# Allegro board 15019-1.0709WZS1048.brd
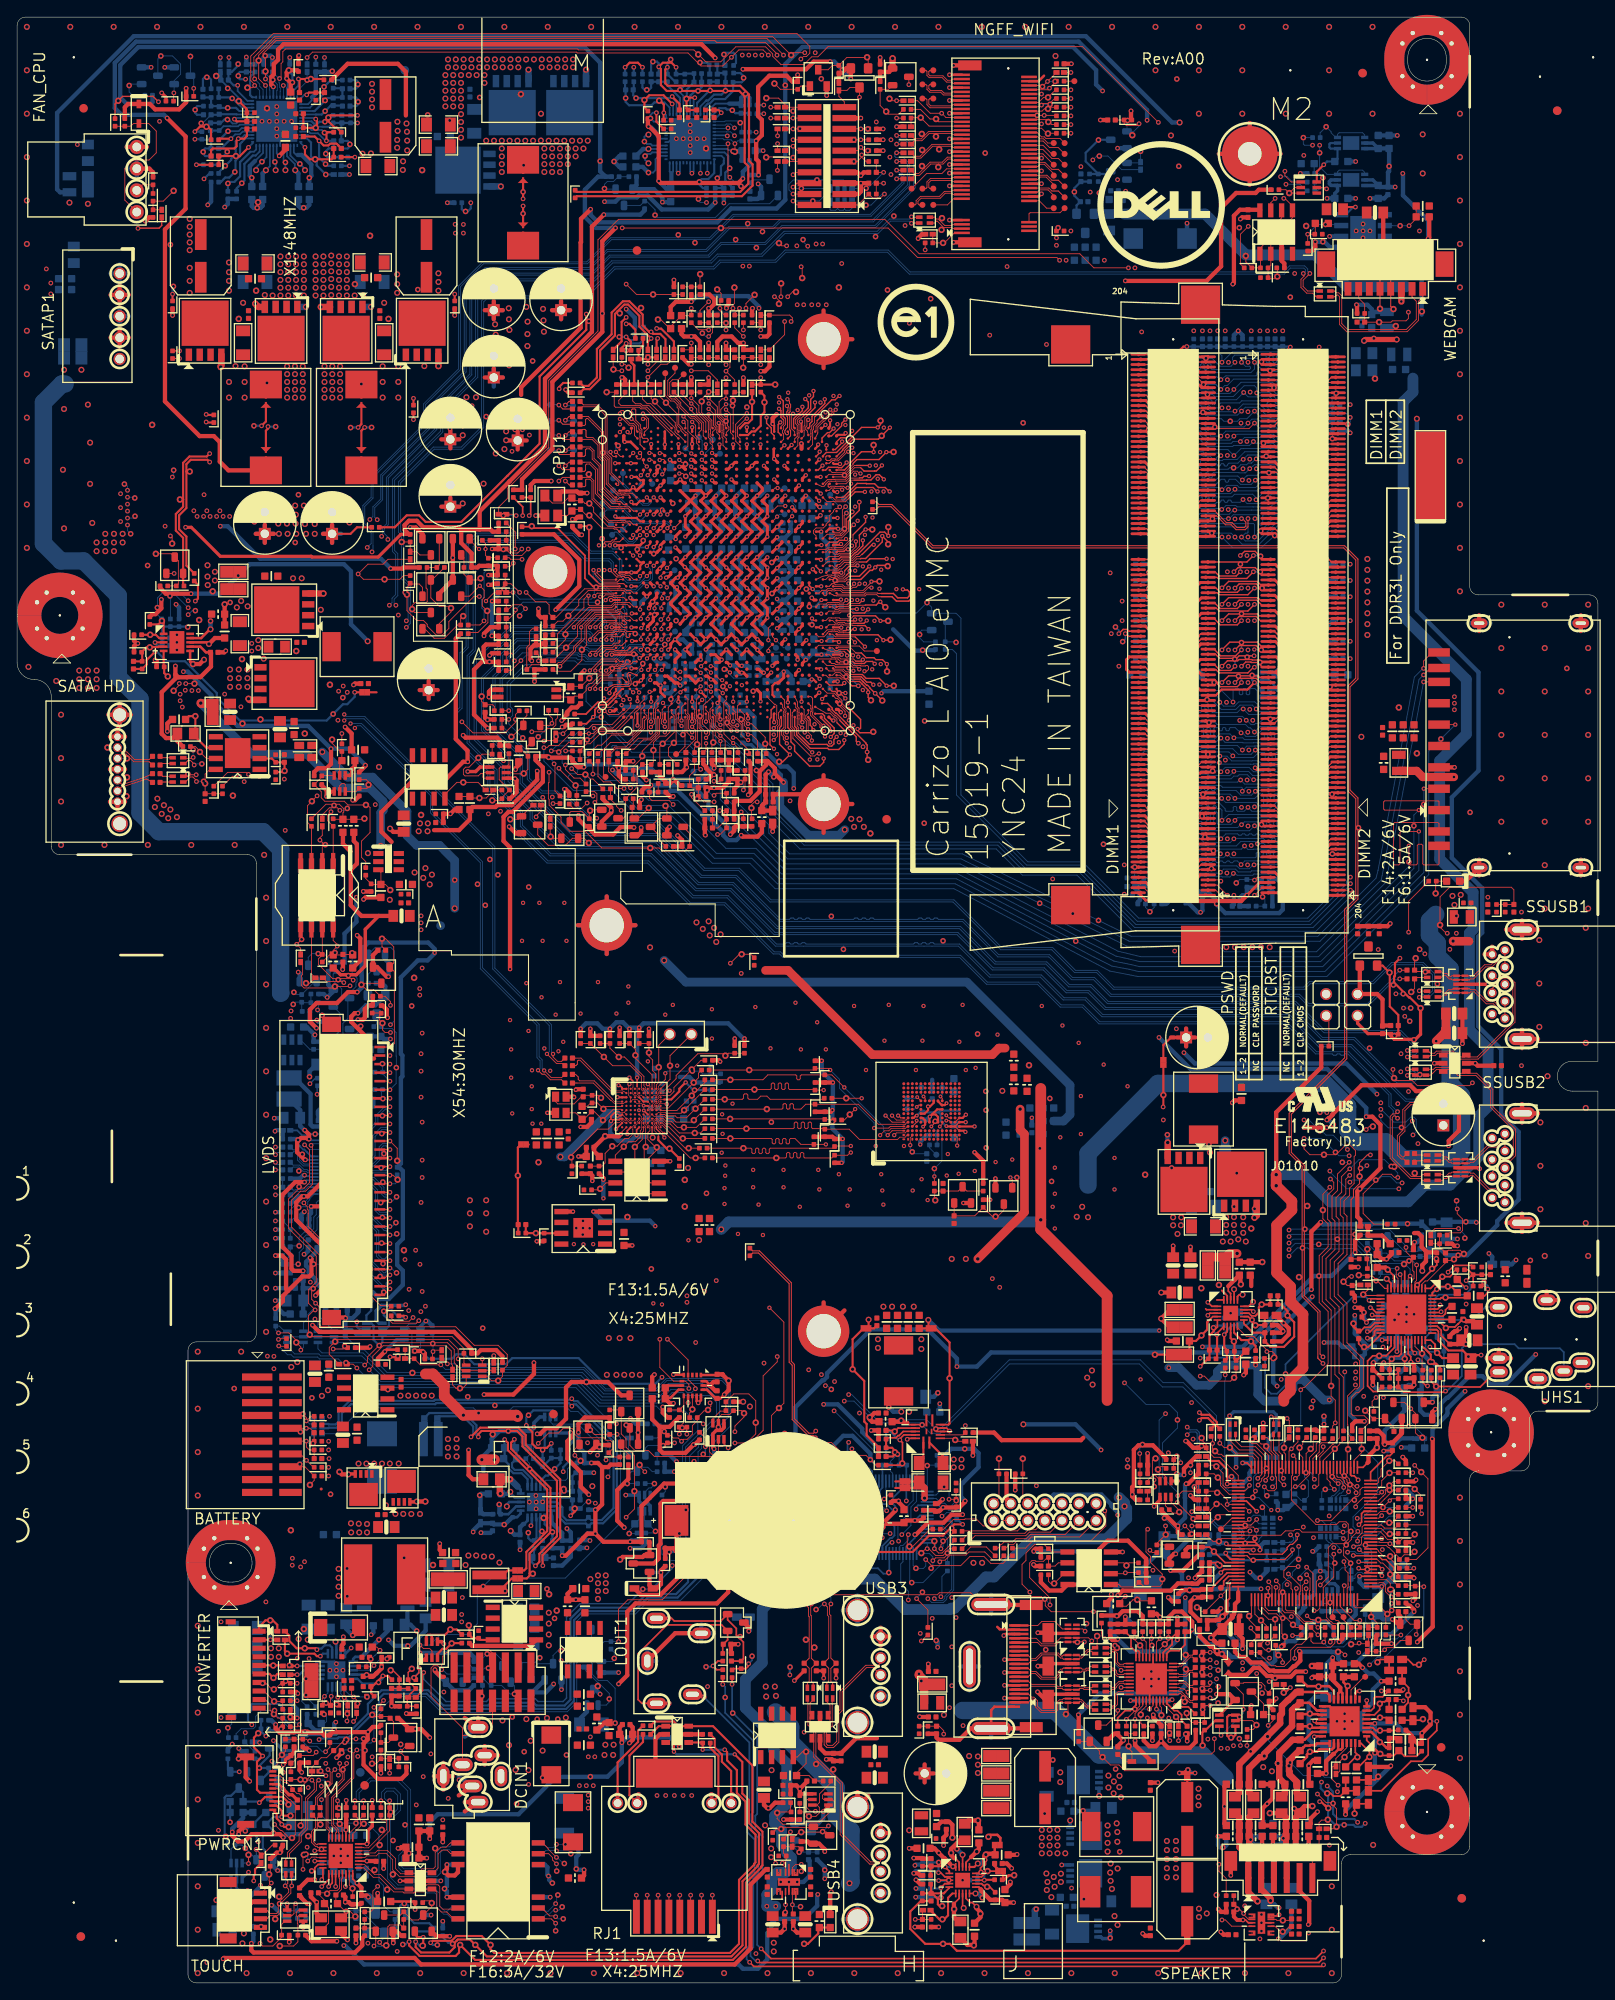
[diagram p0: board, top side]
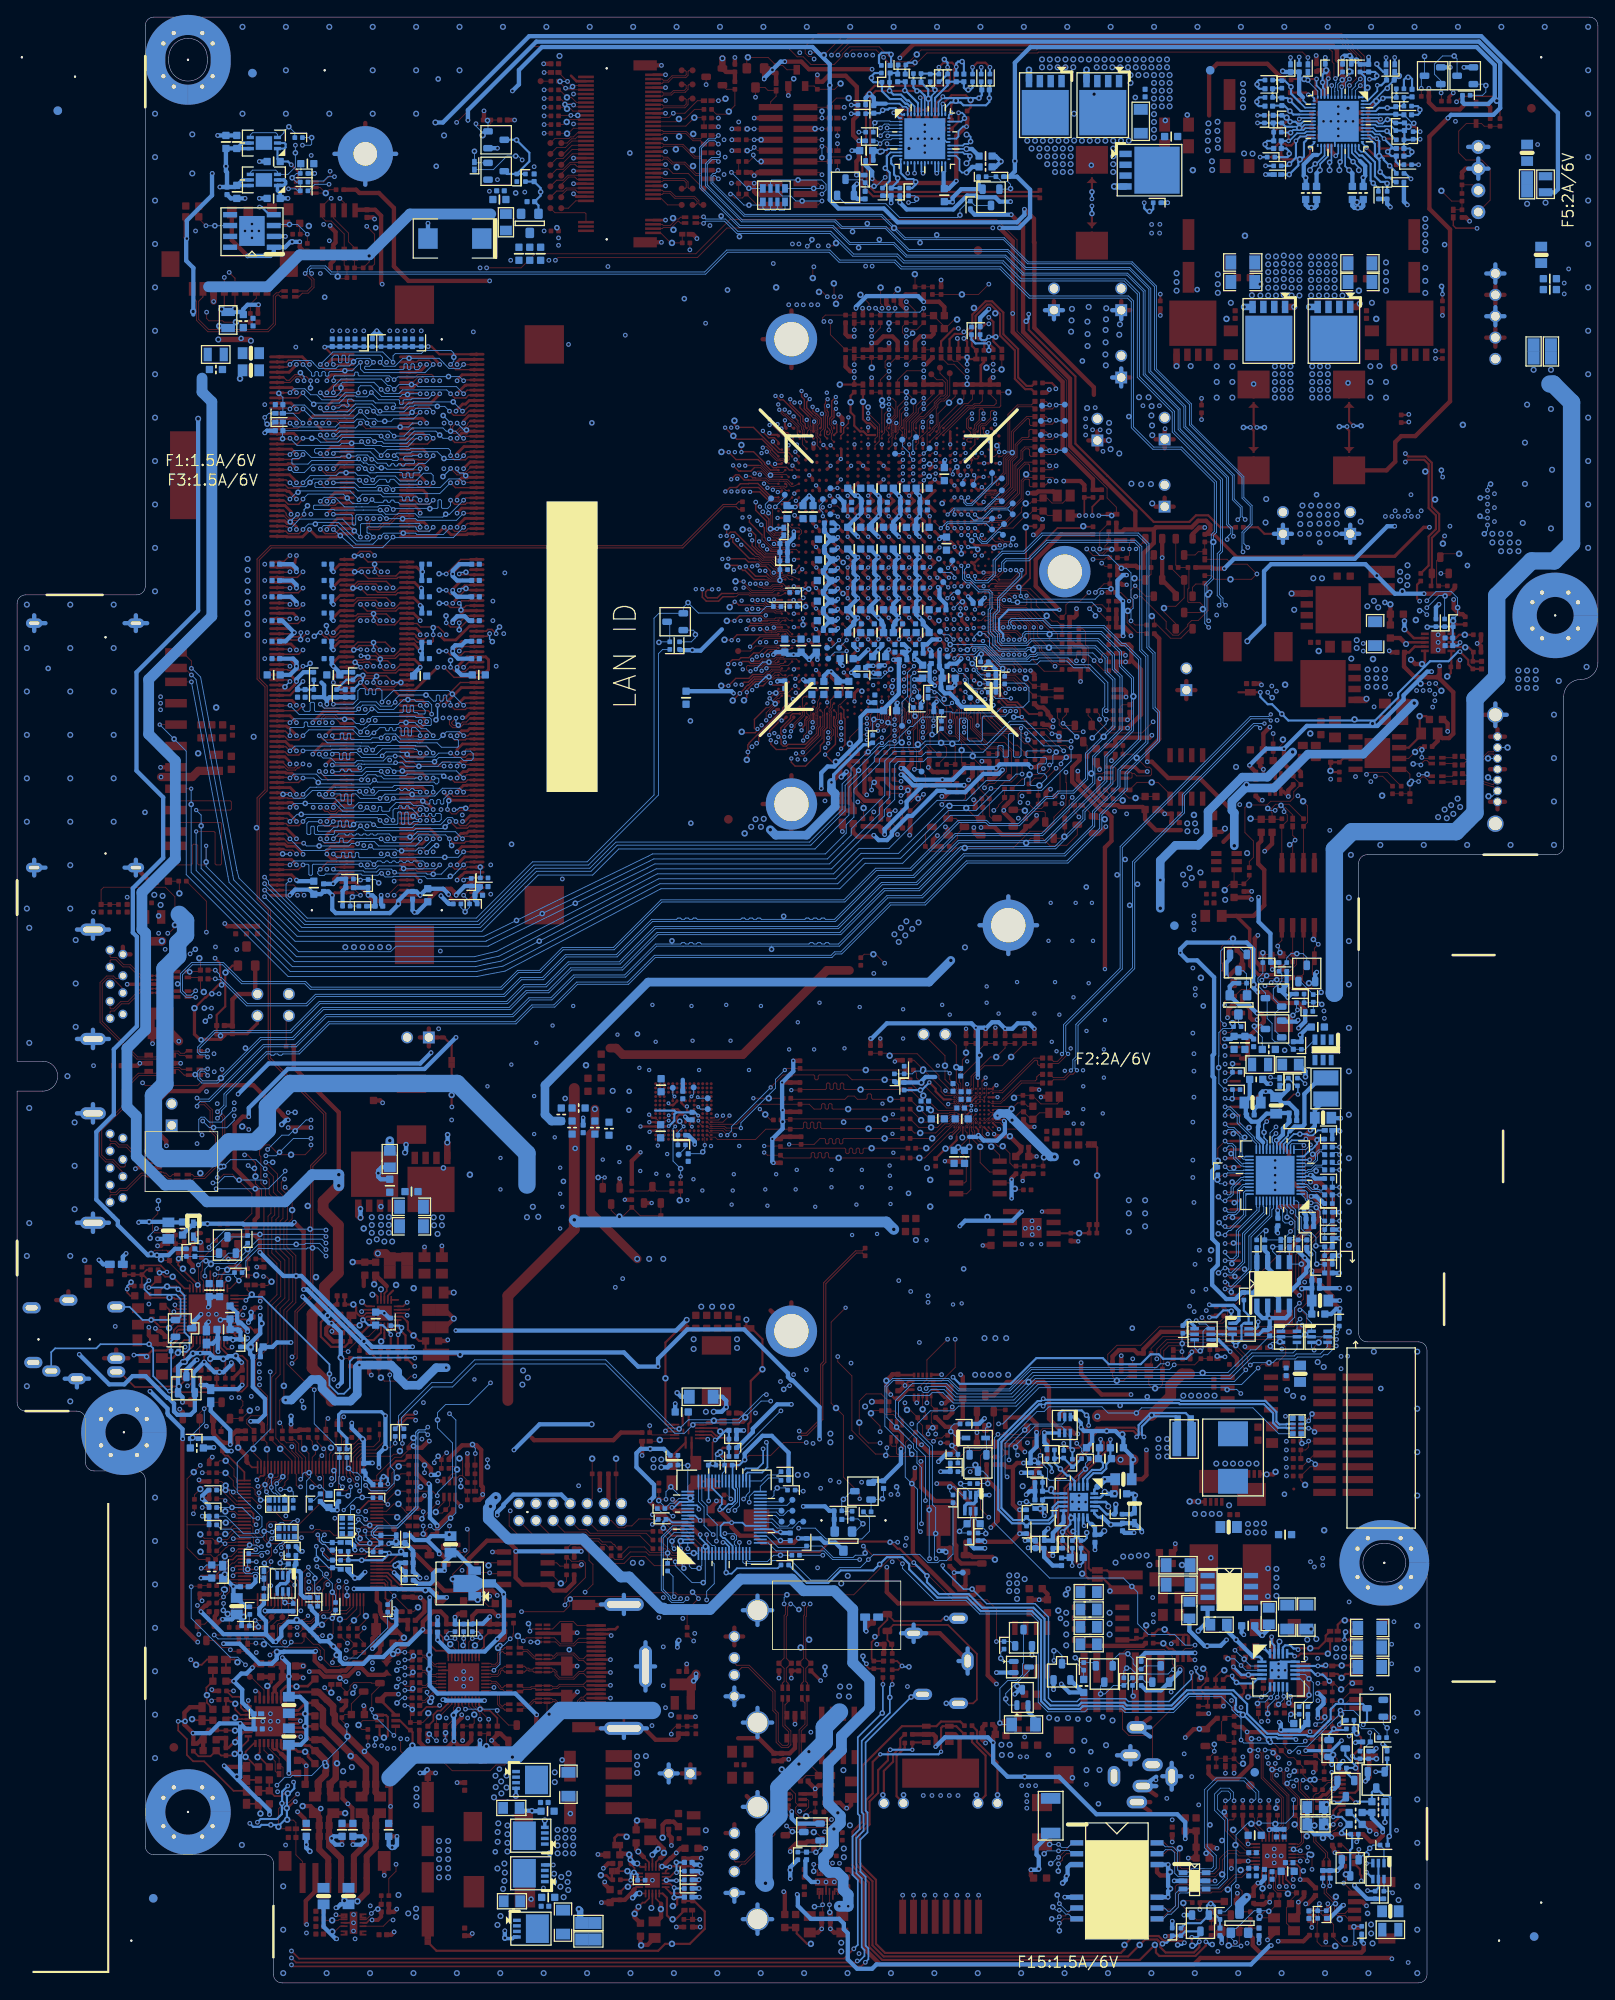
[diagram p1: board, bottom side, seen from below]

Outline 185 x 230 mm; copper layers: TOP, L2GND, L3, L4, L5GND, BOTTOM. Coordinates in mm from the lower left corner of the outline.
Outline path: 0,229 0,154.5 arc(0.59,153.09) 2,152.5 arc(3.41,151.91) 4,150.5 4,133 arc(4.29,132.29) 5,132 27,132 arc(27.71,131.71) 28,131 28,76 arc(27.71,75.29) 27,75 21,75 arc(20.29,74.71) 20,74 20,1 arc(20.29,0.29) 21,0 154,0 arc(154.71,0.29) 155,1 155,14 arc(155.29,14.71) 156,15 169,15 arc(169.71,15.29) 170,16 170,58.9 arc(170.29,59.61) 171,59.9 176,59.9 arc(176.71,60.19) 177,60.9 177,65.9 arc(177.29,66.61) 178,66.9 184,66.9 arc(184.71,67.19) 185,67.9 185,104.34 182,104.34 arc(180.25,106.09) 182,107.84 185,107.84 185,161.4 arc(184.71,162.11) 184,162.4 171,162.4 arc(170.29,162.69) 170,163.4 170,229 arc(169.71,229.71) 169,230 1,230 arc(0.29,229.71) 0,229 ; 24.75,51.4 25.25,51.4 arc(27.5,49.15) 25.25,46.9 24.75,46.9 arc(22.5,49.15) 24.75,51.4 ; 162.75,225.25 arc(165,227.5) 167.25,225.25 167.25,224.75 arc(165,222.5) 162.75,224.75 162.75,225.25

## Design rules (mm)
constraint set DEFAULT: min track width 0.127, pair gap 0.102
net group AUDIO_IO_40: nets RING2 SLEEVE
net group EMMC_POWER_10_10: nets EMMC_VCC1N EMMC_VCC2N
net group EUP-MW: nets EC_EUP EC_EUP_EN
net group GND: nets AMP_GND GND_AUD
net group OSCILLATION-MW: nets LAN_XTALI LAN_XTALO
net group PWR_CHG_SR-DIFF0: nets PWR_CHG_SRN PWR_CHG_SRP
net group SPI_CLK_8-MW: nets SPI_CLK SPI_CLK_1
net group TRANSFORNER_20_10: nets MCT_R_1 XRF_TDC2
net group USB_OC-MW: nets USBOC01* USBOC02*
net group AGND: nets CHG_AGND SIO_AGND TPA3131_GVDD
net group AUDIO_AMP-MW: nets SYNC TPA3131_FAULT# TPA3131_SD TPA3131_SD1#
net group AUDIO_AMP_15: nets AMP_SPKR_L AMP_SPKR_R PORTC_SPK_L PORTC_SPK_L_1 PORTC_SPK_R PORTC_SPK_R_1 SPKR_IN_L SPKR_IN_R TPA3131_GAIN TPA3131_LINN TPA3131_LINN_1 TPA3131_MUTE TPA3131_PLIMIT TPA3131_RINN TPA3131_RINN_1
net group AUDIO_DMIC_MW: nets AUD_DMIC_CLK AUD_DMIC_CLK_R AUD_DMIC_CLK_R_1 AUD_DMIC_DATA AUD_DMIC_DATA_R
net group AUDIO_HDA: nets AUD_BEEP_C AUD_BEEP_R AUD_LINK_BCLK AUD_LINK_RST_N AUD_LINK_RST_N_R AUD_LINK_SDIN AUD_LINK_SDIN_1 AUD_LINK_SDO AUD_LINK_SDO_1 AUD_LINK_SDO_N AUD_LINK_SYNC BUZZER_SPKR_R PCH_AUD_RST_N PCH_AUD_RST_N_1 SENSE_B SLEEVE_G
net group AUDIO_IO: nets AUD_GP3 EAPD_DEPOP HPOL_CON HPOR_CON HPOUT-JD HPOUT-L HPOUT-R LINE2-VREFO LINEOUT-JD LINEOUT-L LINEOUT-R LINEOUT_C-L LINEOUT_C-R LINEOUT_CON-L LINEOUT_CON-R MIC2-L MIC2-L-1 MIC2-R MIC2-R-1 MIC2-VREFO-L MIC2-VREFO-R
net group AUDIO_IO_REF: nets JDREF MIC-CAP VRP
net group AUDIO_SPK_CN: nets SPKR_L+_C SPKR_L+_SNB SPKR_L-_C SPKR_L-_SNB SPKR_OUT_L+ SPKR_OUT_L- SPKR_OUT_R+ SPKR_OUT_R- SPKR_R+_C SPKR_R+_SNB SPKR_R-_C SPKR_R-_SNB TPA3131_BSNL TPA3131_BSNR TPA3131_BSPL TPA3131_BSPR
net group AZ_AUDIO: nets APU_SPKR AZ_BCLK_M AZ_RST_N_M AZ_SDIN1 AZ_SDIN2 AZ_SDOUT_M AZ_SYNC_M
net group CAL_8: nets MEM_MA_ZVDDIO MEM_MB_ZVDDIO P_RX_ZVDD P_TX_ZVDD SATA_CALRN SATA_CALRP USB_COMP_M USBSS_CALRN USBSS_CALRP
net group CHARGER_4_5-MW: nets AC_IN AC_OK# AC_PRES AC_PROTECT AD_IA AD_IA_HW1 AD_IA_HW2 AD_OFF AD_OFF_L BAT_ALERT BAT_IN# BAT_IN#_1 CHG_ON# PD4405_A PD4405_K PQ4206_D PQ4406_2 PQ4406_3 PQ4406_5 PQ4406_6 PQ4409_C PQ4409_E PWR_CHG_AD_OFF PWR_CHG_AD_OFF_R SYS_PRES
net group CLOCK-MWS: nets CK_48M_SIO CK_P_33M_EC CK_P_33M_SIO CLK_48M_SIO_C LPC_CLK0_R LPC_CLK1 LPC_CLK1_R PCH_CLK48_F SUSCLK_32_APU SUSCLK_32_APU_C X32K_X1 X32K_X2 X48M_X1 X48M_X2
net group CONVERTER_4_5-MW: nets LEDC_ISET LPF RT SSTCMP SSTCMP_1 STATUS VREF
net group CONVERTER_10_10: nets ISEN1 ISEN2 ISEN3 ISEN4 ISW OZ554_PWM RTN1 RTN2 RTN3 RTN4
net group CONVERTER_20_10: nets LDR LDR_1 OZ554_VIN SNB
net group DDR3_A_ADDR&CMD-MW: nets M_CAS_A_N M_MAA_A0 M_MAA_A1 M_MAA_A2 M_MAA_A3 M_MAA_A4 M_MAA_A5 M_MAA_A6 M_MAA_A7 M_MAA_A8 M_MAA_A9 M_MAA_A10 M_MAA_A11 M_MAA_A12 M_MAA_A13 M_MAA_A14 M_MAA_A15 M_RAS_A_N M_SBS_A0 M_SBS_A1 M_SBS_A2 M_WE_A_N
net group DDR3_A_CTRL-MW: nets M_ODT_A0 M_ODT_A1 M_SCKE_A0 M_SCKE_A1 M_SCS_A_N0 M_SCS_A_N1
net group DDR3_A_DATA-MW: nets M_DATA_A0 M_DATA_A1 M_DATA_A2 M_DATA_A3 M_DATA_A4 M_DATA_A5 M_DATA_A6 M_DATA_A7 M_DATA_A8 M_DATA_A9 M_DATA_A10 M_DATA_A11 M_DATA_A12 M_DATA_A13 M_DATA_A14 M_DATA_A15 M_DATA_A16 M_DATA_A17 M_DATA_A18 M_DATA_A19 M_DATA_A20 M_DATA_A21 M_DATA_A22 M_DATA_A23 M_DATA_A24 M_DATA_A25 M_DATA_A26 M_DATA_A27 M_DATA_A28 M_DATA_A29 M_DATA_A30 M_DATA_A31 M_DATA_A32 M_DATA_A33 M_DATA_A34 M_DATA_A35 M_DATA_A36 M_DATA_A37 M_DATA_A38 M_DATA_A39 M_DATA_A40 M_DATA_A41 M_DATA_A42 M_DATA_A43 M_DATA_A44 M_DATA_A45 M_DATA_A46 M_DATA_A47 M_DATA_A48 M_DATA_A49 M_DATA_A50 M_DATA_A51 M_DATA_A52 M_DATA_A53 M_DATA_A54 M_DATA_A55 M_DATA_A56 M_DATA_A57 M_DATA_A58 M_DATA_A59 M_DATA_A60 M_DATA_A61 M_DATA_A62 M_DATA_A63
net group DDR3_A_DM-MWS: nets M_MA_DM0 M_MA_DM1 M_MA_DM2 M_MA_DM3 M_MA_DM4 M_MA_DM5 M_MA_DM6 M_MA_DM7
net group DDR3_B_CTRL-MWS: nets M_ODT_B0 M_ODT_B1 M_SCS_B_N0 M_SCS_B_N1
net group DDR3_SEL_4_5-MW: nets SA0_DIM1 SA0_DIM2 SA1_DIM1 SA1_DIM2
net group DP_HPD-MW: nets DP0_HPD DP_HPD HDMI1_DET_APU HDMI1_DET_CON
net group EC_NPCE948L-4_5-MW: nets AC_IN_KBC# AC_OK#_ECIO AD_OFF_ECIO AGPIO84 BAT_IN#_ECIO CHG_ON#_ECIO EC_3P3_CTL EC_3P3_CTL_2 EC_3P3_CTL_3 EC_PSID EC_PWREN ECIO_IO_SMI_N ECIO_LPC_PME_N JENK# MODEL_ID_DET PCB_VER_ID RDY# SLP_S3_N_EC SLP_S5_N_EC TCK TDI TDO TMS
net group EMMC_CLK-MW: nets EMMC_CLK EMMC_CLK_C EMMC_CLK_M EMMC_RCLK EMMC_RCLK_M
net group EMMC_CLOCK-MWS: nets SATA_X1 SATA_X2 SATA_X2_R
net group EMMC_CMD-MWS: nets EMMC_CMD EMMC_CMD_C EMMC_CMD_M
net group EMMC_DAT-MWS: nets EMMC_D0 EMMC_D1 EMMC_D2 EMMC_D3 EMMC_D4 EMMC_D5 EMMC_D6 EMMC_D7 EMMC_DATA_0 EMMC_DATA_1 EMMC_DATA_2 EMMC_DATA_3 EMMC_DATA_4 EMMC_DATA_5 EMMC_DATA_6 EMMC_DATA_7
net group EMMC_RST_EN-MWS: nets EMMC_REXT EMMC_VDDI LDO_VDD33_18 RST# WR2_EN
net group FAN_PWM: nets BKLT_ADJ CPU_FAN_CTRL_SIO CPU_FAN_TACH_SIO DPLVDS_PWMIN DPLVDS_PWMOUT LVDS_BL_ADJ SIO_LVDS_BL_ADJ
net group FCH_SW_4-MW: nets 0.775V_TRACK_GATE APU_S5_MUX_CTRL_D APU_S5_MUX_CTRL_R COMP_OUT1 COMP_OUT2 FCH_S5_POWER_COMP VDDNB_TRACK_GATE
net group FFS_4_5-MW: nets FALL_INT2 FFS_INT1 FFS_INT1_C FFS_INT2_APU FFS_INT2_C FFS_INT2_Q
net group GPIO_4-MW: nets ADAPTOR_PSID ADAPTOR_PSID_R AGPIO3 AGPIO8 AGPIO11 AGPIO13 AGPIO14 AGPIO15 AGPIO24 AGPIO40 AGPIO66 AGPIO88 AGPIO89 BIST_DISABLE BIST_EN_INV BIST_ENABLE BIST_ENABLE_1 BOARD1 BOARD2 BOARD3 CORETYPE DP_2K_ZVSS DP_150_ZVSS DP_STEREOSYNC DP_STEREOSYNC_PU DPLVDS_HPD EAPD_DEPOP_1 EC_IMS EGPIO67 EGPIO70 EGPIO119 EGPIO131 EGPIO132 EGPIO145 GP11 GP14 GP24 GP26 GP27 GP32 GP33 GP34 GP63 IO_SMI_N JACK_PSID LAN_DISABLE_N LPC_PME_N LVDS_DET_A* LVDS_DET_B* MINI_POWER_CTRL MPCIE_DISABLE_N NGFF_BT_DISABLE NGFF_DETECT_PCIE NGFF_DETECT_PCIE_C NGFF_DETECT_USB NGFF_DETECT_USB_C OSD_BIST_N OSD_DN OSD_DN_R OSD_MENU OSD_MENU_R OSD_MENU_SIO OSD_UP OSD_UP_R PSID_D PSID_D_1 PSID_G PW_CLEAR PWRCN_DET_N S0A3_GPIO S0A3_GPIO_G SIO_HDD_LED SIO_HDD_LED_1 SKEW1 SKEW2 SKEW3 SMBUS_ISP_G SPKR_DET SPKR_DET_C VDD_095_FB_H_CTL VDDGFX_PD WEBCAM_DET
net group HDMI-MW: nets CFG DCIN_EN DDCBUF EQ ISET PD_N PRE REXT SB5_33_CT1 SB5_33_CT2 VCC5_DDC_HDMI
net group HDMI_DDA-MW: nets HDMI1_DATA_APU HDMI1_DATA_APU_SRC HDMI1_DATA_CON
net group HDMI_DDC-MW: nets HDMI1_CLK_APU HDMI1_CLK_APU_SRC HDMI1_CLK_CON
net group HDMI_PWR: nets V_5P0_HDMI_CONN_L
net group HDT-MW: nets APU_ALERT# APU_DBRDY APU_DBREQ APU_DBREQ# APU_SVD APU_SVT APU_TCK APU_TDI APU_TDO APU_TMS APU_TRST HDT_C_M1 HDT_C_M2 HDT_C_M3 HDT_PW_M3 HDT_PW_M4 HDT_RST0 HDT_RST1 HDT_TRST HDT_VDDIO_SUS
net group LAN_OTHER_4-5-MW: nets LAN_RSET LANCLK_REQ_N LANCLK_REQ_U_N RTL_ISOLATE_N RTL_ISOLATE_N_1 RTL_ISOLATE_N_2
net group LED_10_6: nets APU_SATA_LED_N BATT_AMBER_LED# BATT_AMBER_LED#_C BATT_WHITE_LED# BATT_WHITE_LED#_C LAN_LEDACT_R# LINK_ACTIVITY_N LINK_PWR PB_IN_SW1 PCH_SATA_LED_1 PCH_SATA_LED_R PWR_LED_YELLOW_C PWR_LED_YELLOW_C2 SATA_LED_N_C_1 SIO_GREEN SIO_GREEN_PWM SIO_GREEN_PWM_C_1 SIO_YELLOW SPEED_100*_CON SPEED_100_N SPEED_1000*_CON SPEED_1000_N SUS_LED_GREEN_C SUS_LED_GREEN_C2
net group LPC-MW: nets EXT_RST# FWH_ID0 INIT_3V LAD0_FWH0 LAD0_FWH0_EC LAD1_FWH1 LAD1_FWH1_EC LAD2_FWH2 LAD2_FWH2_EC LAD3_FWH3 LAD3_FWH3_EC LDRQ# LDRQ#_EC LFRAMEJ_FW4 LFRAMEJ_FW4_EC LPC_PD_N LPC_TPM PLTRST*_EC SER_IRQ
net group M_EVENT_4_5-MW: nets MEM_MA_EVENT_L SIO_MEM_EVENT_L SIO_MEM_EVENT_L_B SIO_MEM_EVENT_L_C
net group MEM_VREF: nets APU_M_VREF_SUS APU_M_VREFDQ_SUS DIMM_APU_VREF DIMM_DQ_APU_VREF_MA DIMM_DQ_APU_VREF_MB MEM_VREFCA_SUS
net group NGFF_CLCCK-MW: nets NGFF_CLKREQ0_N NGFF_CLKREQ1_N SUSCLK_NGFF
net group NGFF_OTHER-MW: nets NGFF_ALERT# NGFF_ALERT_N NGFF_CLKREQ0_NGFF# NGFF_CLKREQ1_APU# NGFF_CLKREQ1_N_TP NGFF_PEWAKE0_N NGFF_POWER_CTRL_1 NGFF_W_DISABLE1_N NGFF_W_DISABLE2_N
net group OTHER_4_5-MW: nets 1117_ADJ APU_PROCHOT# APU_PWNBTN_N APU_SIC APU_SID APU_SVC APU_VDD_33_18_SEL ECIO_APU_PROCHOT# GFX_SVC GFX_SVD GFX_SVT KDAT MCLK MDAT PB_IN_N_1 PB_IN_N_2 PME#_M SVC_VDD SVC_VDD_GFX SVD_VDD SVD_VDD_GFX SVT_VDD SVT_VDD_GFX SYS_FAN_TACH1_1 SYS_FAN_TACH1_2 SYSTEM_FAN_PWM1_1 TP_DET VR_HOT WAKE_N_APU
net group OZ778_GPIO-MW: nets OGPIO0 OGPIO1 OGPIO2 OGPIO3 OGPIO4 OGPIO5
net group PANEL_CONTROL-MW: nets APU_LVDS_BL_ADJ BIST_EN_SIO BIST_PIN25 BKLT_EN BKLT_EN1 BUFFER1_M4 DPLVDS_BL_EN DPLVDS_PANEL_VCC LVDS_BL_EN_1 LVDS_DET_B_C* LVDS_PU_5 LVDS_PU_5_1 LVDS_PU_5_2 LVDS_PU_6 LVDS_PU_24 PANEL_ON_1 PANEL_ON_2 PANEL_ON_3 PANEL_ON_4 PANEL_ON_5 PANEL_SEL1_CABLE PANEL_SEL1_CABLE_EC PANEL_SEL2_CABLE PANEL_SEL2_CABLE_EC PANEL_SEL3_CABLE PANEL_SEL3_CABLE_EC S_LVDS_BL_EN SCALAR_SIO_PU
net group POWER_10_10: nets COMPNB_R PWR_FCH_S5 SIO_VREF VBAT_SB_N VBAT_SIO
net group POWER_40_5: nets 3D3V_AUX_EC AVCC_EC HM_VCCP HM_VCCP_R SIO_AVCC3 SIO_MAIN_VCC3 SIO_VCORE
net group POWER_50_5: nets 3V_VA +3VL +5VL AVCC33_2136 DVCC33_2136 SWR_LX SWR_V12 USBVCC01_E V_5_CODEC
net group POWER_OTHER_40_5: nets 1P5V_LPS_APU 3D3V_RUN_FFS 19V_AMP_AVCC 19V_AMP_PVCC APU_VDDIO_AZ FCH_0.775_S5 RT9025_ADJ V_1P5_HDMI
net group POWER_RTC_35_5: nets VBAT1 VBAT1_R VBAT2
net group PWM_10_10: nets 1P5_5930_FB 1P5_5930_VCNTL AD+_G_1 AD+_G_2 AUD_LINK_RST_N_2 BIST_DISABLE_1 BIST_EN DC_IN_D DDR_VREF_S3 DIFFNB_R EAPD_DEPOP_2 ILIM_R ILIMNB_R LAN_DISABLE_N_1 LAN_DISABLE_N_2 LED_5VSB OSD_BIST_N_1 PWR_1D8V_EN PWR_1D8V_FB PWR_1D8V_VCC PWR_3D3V_ENTRIP2 PWR_3D3V_FB PWR_3D3V_FB2 PWR_5V3V_EMN PWR_5V3V_PGOOD PWR_5V3V_TON PWR_5V_ENTRIP1 PWR_5V_FB1 PWR_CHG_ACDET PWR_CHG_CMPIN PWR_CHG_CMPIN_R PWR_CHG_CMPIN_RR PWR_CHG_IOUT PWR_CHG_NC PWR_COMP_R PWR_CPU_COMP PWR_CPU_COMPNB PWR_CPU_CSCOMP PWR_CPU_CSCOMPNB PWR_CPU_CSP1 PWR_CPU_CSP1NB PWR_CPU_CSP2 PWR_CPU_CSP2NB PWR_CPU_CSREF PWR_CPU_CSREFNB PWR_CPU_CSSUM PWR_CPU_CSSUMNB PWR_CPU_DIFF PWR_CPU_DIFFNB PWR_CPU_DROOP PWR_CPU_DROOPNB PWR_CPU_FB PWR_CPU_FBNB PWR_CPU_ILIM PWR_CPU_ILIMNB PWR_CPU_IOUT PWR_CPU_IOUTNB PWR_CPU_PHCONFIG PWR_CPU_ROSC PWR_CPU_SR PWR_CPU_TEENSE PWR_CPU_TSENSENB PWR_CPU_VRMP PWR_DIFF_R PWR_GFX_COMP PWR_GFX_COMP_FB PWR_GFX_CSCOMP PWR_GFX_CSP1 PWR_GFX_CSP2 PWR_GFX_CSREF PWR_GFX_CSSUM PWR_GFX_DIFF PWR_GFX_DIFF_R PWR_GFX_DROOP PWR_GFX_FB PWR_GFX_ILIM PWR_GFX_ILIM_R PWR_GFX_IOUT PWR_GFX_PHCONFIG PWR_GFX_ROSC PWR_GFX_SR PWR_GFX_TSENSE PWR_GFX_VR_HOT PWR_GFX_VRMP PWR_GFX_VSS PWR_VDDP_CS PWR_VDDP_EN PWR_VDDP_FB PWR_VDDP_FB_R PWR_VDDP_PG PWR_VDDP_RF PWR_VDDQ_CS PWR_VDDQ_EN PWR_VDDQ_FB PWR_VDDQ_SENSE PWR_VDDQ_TON PWR_VDDQ_VDD PWR_VDDQ_VDDP PWR_VDDQ_VTTREF PWR_VTT_EN RT9025_ADJ_FB VREG_PCIAUX_PCH VREG_PCIAUX_PCH_1
net group PWM_20_10: nets AUD_REGREF BQ24737_REGN CBN CBP CPU_BST1_SW1 CPU_BST2_SW2 CPVEE D2_M DPLVDS_PIN12 DPLVDS_PIN16 PWR_1D8V_BOOT PWR_1D8V_BOOT_A PWR_1D8V_FB_1 PWR_1D8V_VOUT PWR_3D3V_BOOT2 PWR_3D3V_BOOT2_R PWR_3D3V_LDO3 PWR_5V3V_ENLDO PWR_5V3V_LDO5 PWR_5V_BOOT1 PWR_5V_BOOT1_R PWR_5V_BYP1 PWR_5V_SNB PWR_CHG_BTST PWR_CHG_BTST_1 PWR_CHG_ILIM PWR_CPU_BST1 PWR_CPU_BST2 PWR_GFX_BST1 PWR_GFX_BST1_SW1 PWR_VDDP_BOOT_R PWR_VDDQ_BOOT PWR_VDDQ_BOOT_L PWR_VDDQ_SNB SIO_VIN2 SIO_VIN3 SIO_VIN4 SIO_VIN5 V_0P675_S3 VREF_1
net group PWM_30_12: nets PWR_CHG_VCC PWR_CPU_VCC PWR_CPU_VDD PWR_CPU_VDDNB PWR_GFX_VCC PWR_GFX_VDD
net group PWM_PHASE: nets PWR_3D3V_LGATE2 PWR_3D3V_UGATE2 PWR_5V_LGATE1 PWR_5V_UGATE1 PWR_CHG_HIDRV PWR_CHG_LODRV PWR_CPU_HG1 PWR_CPU_HG2 PWR_CPU_LG1 PWR_CPU_LG2 PWR_GFX_HG1 PWR_GFX_LG1 PWR_VDDP_LGATE PWR_VDDP_UGATE PWR_VDDQ_LGATE PWR_VDDQ_UGATE
net group PWR_EN_4-MW: nets 0D95V_S0_EN 0P95V_MAIN_APU_M 1P5_5930_EN APU_DIS_1 APU_DIS_2 APU_DIS_3 APU_S5_MUX_CTRL EVAL_PE_L EVAL_PWREN EVAL_PWRGD OZ554_ENA PWR_FCH_REF PWR_FCH_VCNTL RUN_0P95_EN1 RUN_0P95_EN2 RUN_0P95_EN3 RUN_0P95_EN4 RUN_EN1 RUN_EN2 RUN_EN_1P8V RUNPWR_R6 SB3V_EN SIO_AMD_SVID_EN V_VCORE_EN VCC5_33_CT1 VCC5_33_CT2 VCC5_33_EN VDDGFX_EN VDDGFX_EN_1 VDDGFX_EN_2
net group PWR_EN_4_10-MW: nets USB_EN USB_EN1 USB_EN2 VBYP_2
net group PWRGD&RST_4-MW: nets 1D5V_S3_PG_1 1P5_5930_PG 1P5V_S3_PG 1P8V_PWR_PG 3V_5V_POK APU_PWRGD APU_PWRGD_BUF APU_VRM_PWRGD DDR3_DRAMRST_N DDR3_DRAMRST_N_A_1 DDR3_DRAMRST_N_B_1 EMMC_RESET# EMMC_RESET#_1 EMMC_RESET#_M EMMC_RESET_SIO FP_RST_N GFX_VRM_PWRGD ICH_RSMRST_N_R KBRST_N LAN_DISABLE_N_3 LAN_DISABLE_N_4 LAN_DISABLE_V3 LDT_RST LDT_RST#_BUF NB_VRM_PWRGD NGFF_POWER_CTRL_V2 PCIE_RST# PCIE_RST_N PCIE_RST_N_A PCIRST1# PCIRST3# PLTRST*_SIO PLTRST_LAN_N PLTRST_N PWRBTN_N PWRGD_3V PWRGD_3V_B_1 PWRGD_3V_D PWRGD_3V_G PWRGD_3V_LL PWRGD_PS_L PWRGD_PS_L1 PWRGD_PS_L2 PWROK3_1 PWROK3_1_R PWROK3_2 PWROK3_2_R RSMRST*_R RSMRST_N RSMRST_N_1 RSMRST_N_FCH SIO_PCIRSTIN# SIO_PSON_N SLP_S3_N SLP_S3_N_1 SLP_S3_N_G SLP_S3_N_R SLP_S3_N_R3 SLP_S3_N_R_1 SLP_S3_N_R_2 SLP_S3_N_R_3 SLP_S5_N SLP_S5_N_C SYS_PWRGD SYS_PWRGD_G SYS_PWRGD_HV SYS_PWRGD_HV_1 SYS_PWRGD_HV_2 VCORE_PWROK VDDGFX_PWROK WAKE_N
net group SD_CARD-MWS: nets SD_CD_BD SD_CLK_BD SD_CLK_CH_C SD_CMD_BD SD_CMD_CH_C SD_DATA0_BD SD_DATA0_CH_C SD_DATA1_BD SD_DATA1_CH_C SD_DATA2_BD SD_DATA2_CH_C SD_DATA3_BD SD_DATA3_CH_C SD_LED_BD SD_LED_BD_A SD_PWRCTL_CH SD_WP_BD
net group SENSE_4-MW: nets VDDCR_CPU_SENSE VDDCR_GFX_SENSE VDDCR_NB_SENSE VDDP_SENSE
net group SIO_IT8739-4_5-MW: nets EC_A20GATE EC_HDMI_PD_N EC_LAN_DISABLE_N IMS KBCLK SIO_ATXPG SIO_CE_N SIO_CLK_DB SIO_COPEN# SIO_DAT_DB SIO_EUP_EN# SIO_HOLD# SIO_INT# SIO_INT_C SIO_PWNBTN_N SIO_SCK SIO_SCK_R SIO_SI SIO_SO SIO_VIN1 SIO_WP# SIO_WRST# SW_ON_N_SIO SYS_3VSB
net group SIO_IT8739-4_12-MW: nets A20GATE
net group SIO_OZ778-4-MW: nets NC#7 SPI_CS# SPI_MISO SPI_MOSI SPI_SCK
net group SMBUS-MW: nets BATA_SCL_1 BATA_SDA_1 DPLVDS_EDIDCLK DPLVDS_EDIDCLK_C DPLVDS_EDIDSDA DPLVDS_EDIDSDA_C DPLVDS_FWCLK DPLVDS_FWSDA DPLVDS_ISPCLK DPLVDS_ISPDAT EC_SMB2_CLK EC_SMB2_DATA ISP_CLK1 ISP_DAT1 M1_SMB_CLK M1_SMB_DATA SIO_DEBUG_RX SIO_DEBUG_TX SIO_SMB2_CLK SIO_SMB2_DATA SIO_SMCLK0 SIO_SMCLK0_D SIO_SMDAT0 SIO_SMDAT0_D SMB0_CLK SMB0_CVT_CLK SMB0_CVT_DATA SMB0_DATA SMB1_CLK SMB1_DATA SMBUS_ISP SMBUS_MS
net group SPI-MW: nets ROM_RST# SPI_33_18_PU1 SPI_33_18_PU2 SPI_CS0_N SPI_DATAIN SPI_DATAOUT SPI_MISO_ROM_1 SPI_MOSI_1 SPI_WP# SST_HOLDJ_1 SST_HOLDJ_1_R
net group TP-MW: nets APU_TEST0 APU_TEST1 APU_TEST2 APU_TEST4 APU_TEST5 APU_TEST6 APU_TEST9 APU_TEST10 APU_TEST11 APU_TEST14 APU_TEST15 APU_TEST16 APU_TEST17 APU_TEST28_H APU_TEST28_L APU_TEST31 APU_TEST37 APU_TEST410 APU_TEST411 EC_SCI EC_VCORF EMMC_E9 EMMC_E10 EMMC_F10 EMMC_K10 RSVD_AN30 RSVD_U30 RSVD_U31 T_DP_BLON T_DP_DIGON TEMPIN0 TEMPIN1 TEMPIN2 TEMPINR TEST18_M TEST19_M TP_NGFF_COEX1 TP_NGFF_COEX2 TP_NGFF_COEX3 TP_NGFF_LED1 TP_NGFF_LED2 TP_NGFF_MLDIR UART0_RXD UART0_TXD USBCLK_TP
net group VRD_10_10: nets VSS_SENSE
net group WLAN_CLINK_4_10-MW: nets CLINK_CLK_LAN CLINK_DATA_LAN CLINK_RST_LAN_N

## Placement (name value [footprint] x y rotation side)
AFTP1  AFTE14P-GP  [AFTE14P-75]  35.59 57.78 0 top
BAT2  ACES-CONN20G-GP  [50290-0100N-001]  32 64.14 270 top
BT1  BAT-AAA-BAT-034-K01-GP  [AAA-BAT-034-K01]  83.37 54.11 180 top
BTRST1  JOWLE-CON2-5-GP  [A2541WV0-1EX2PA-6T]  156.88 114.43 270 top
C1  SCD1U16V2KX-3DLGP  [C402H22]  157.39 194.31 0 bottom
C2  SC10U6D3V3MX-DL-GP  [C603H36]  41.31 109.98 0 bottom
C3  SC10U6D3V3MX-DL-GP  [C603H36]  42.58 109.98 0 bottom
C4  SC4D7U10V3KX-DL-GP  [C603H36]  40.8 39.29 90 top
C5  SCD47U25V3KX-1-DL-GP  [C603H36]  34.83 30.35 90 bottom
C6  SCD1U16V2KX-3DLGP  [C402H22]  40.29 109.98 0 bottom
C7  SC1U10V2KX-1GP  [C402H22]  34.07 86.49 180 bottom
C8  SC1KP50V2KX-1DLGP  [C402H22]  40.95 34.67 270 top
C9  SC1U10V2KX-1GP  [C402H22]  31.53 86.11 90 bottom
C10  SC100P50V2JN-3DLGP  [C402H22]  38.01 38.61 0 top
C11  SC1U10V2KX-1GP  [C402H22]  31.53 83.06 90 bottom
C14  SCD01U50V2KX-1DLGP  [C402H22]  35.64 109.68 180 bottom
C15  SC1KP50V2KX-1DLGP  [C402H22]  141.38 191.9 0 bottom
C20  SC4D7U10V3KX-DL-GP  [C603H36]  32.77 111.84 270 bottom
C32  SCD1U25V3ZY-1-LL-GP  [C603H36]  50.55 50.34 270 top
C33  SC27P50V2JN-2-LL-GP  [C402H22]  44.71 34.01 0 top
C35  SC330P100V3JN-GP  [C603H36]  40.93 41.78 270 bottom
C36  SC1U100V6KX-3-GP  [C1206H75]  34.12 42.8 0 bottom
C37  SC1U100V6KX-3-GP  [C1206H75]  36.36 42.8 0 bottom
C38  SC1U100V6KX-3-GP  [C1206H75]  26.7 39.24 90 bottom
C39  SC1U100V6KX-3-GP  [C1206H75]  26.7 36.96 90 bottom
C40  SC1U100V6KX-LL-GP  [C1206H71]  26.7 41.53 90 bottom
C41  SCD1U16V2KX-3DLGP  [C402H22]  65.44 177.04 270 top
C42  SCD1U16V2KX-3DLGP  [C402H22]  65.44 177.93 270 top
C43  SCD1U25V2KX-LL-GP  [C402H22]  38.26 34.92 180 top
C44  SCD1U16V2KX-3DLGP  [C402H22]  65.44 176.15 270 top
C45  SCD1U16V2KX-3DLGP  [C402H22]  65.44 175.26 270 top
C46  SCD1U16V2KX-3DLGP  [C402H22]  131.35 159.38 90 bottom
C48  SC10U25V5KX-DL-GP  [C805H58]  8.29 214.12 0 bottom
C50  SC5D6P50V2CN-1DLGP  [C402H22]  65.95 171.96 0 top
C52  SC5D6P50V2CN-1DLGP  [C402H22]  65.95 173.86 180 top
C55  SC4D7U6D3V3KX-DLGP  [C603H36]  137.83 152.91 90 bottom
C57  SC10P50V2JN-4DLGP  [C402H22]  65.95 152.15 180 top
C58  SC8P50V2DN-1DL-GP  [C402H22]  65.95 150.11 0 top
C60  SCD1U16V2KX-3DLGP  [C402H22]  131.35 156.97 90 bottom
C61  SCD01U25V2KX-3GP  [C402H22]  68.99 138.68 270 top
C65  SC1KP50V2KX-1DLGP  [C402H22]  145.7 150.88 0 bottom
C66  SC100P50V2JN-3GP  [C402H22]  80.17 139.83 90 top
C67  SCD01U16V2KX-3GP  [C402H22]  72.42 137.54 90 top
C72  SC10U6D3V3MX-DL-GP  [C603H36]  162.21 146.43 180 top
C73  SC4D7U6D3V3KX-GP  [C603H36]  163.48 146.43 0 top
C74  SCD1U16V2KX-3GP  [C402H22]  159.8 146.43 0 top
C75  SC2D2U10V3KX-1DLGP-U  [C603H36]  160.94 146.43 180 top
C76  SC150P50V2JN-3DLGP  [C402H22]  149.51 56.77 0 bottom
C77  SCD01U25V2KX-3GP  [C402H22]  78.27 143.51 0 top
C78  SC1U10V2KX-1DLGP  [C402H22]  62.26 159.77 270 top
C84  SCD1U16V2KX-3DLGP  [C402H22]  37.63 17.53 180 bottom
C87  SCD1U16V2KX-3GP  [C402H22]  43.82 34.01 0 top
C88  SCD1U16V2KX-3GP  [C402H22]  44.1 30.96 90 top
C91  SCD1U16V2KX-3DLGP  [C402H22]  163.1 117.47 90 top
C94  SCD1U25V3KX-GP  [C603H36]  52.99 138.05 0 top
C95  SC10U10V5KX-2GP  [C805H54]  45.25 135.64 0 top
C99  SC1U10V2KX-1DLGP  [C402H22]  158.15 123.19 180 top
C100  SC1U10V2KX-1GP  [C402H22]  159.42 123.19 180 top
C101  SCD1U16V2KX-3DLGP  [C402H22]  49.44 135.76 90 top
C103  SCD1U16V2KX-3DLGP  [C402H22]  144.05 207.01 0 top
C104  SC10U10V5KX-2DLGP  [C805H50]  168.18 111.12 90 top
C105  SC10U10V5KX-2GP  [C805H54]  168.18 113.41 270 top
C106  SCD1U16V2KX-3GP  [C402H22]  172.12 125.73 180 top
C109  SC10U6D3V3MX-DL-GP  [C603H36]  5.62 199.39 90 bottom
C110  SC1U25V3KX-1-DLGP  [C603H36]  5.62 198.12 90 bottom
C111  SCD1U16V2KX-3DLGP  [C402H22]  163.1 97.03 90 top
C112  SC10U10V5KX-2DLGP  [C805H50]  6.64 202.18 0 bottom
C113  SCD1U16V2KX-3DLGP  [C402H22]  163.1 96.01 90 top
C121  SC100P50V2JN-3GP  [C402H22]  156.12 84.2 180 top
C122  SCD1U16V2KX-3DLGP  [C402H22]  65.44 185.04 270 top
C126  SC22P50V2JN-4GP  [C402H22]  163.41 85.34 0 top
C127  SC10U6D3V3MX-DL-GP  [C603H36]  159.93 86.49 270 top
C129  SC10U6D3V3MX-DL-GP  [C603H36]  159.16 84.45 180 top
C130  SCD1U25V2KX-GP  [C402H22]  167.17 84.96 0 top
C131  SCD1U16V2KX-3DLGP  [C402H22]  161.27 85.45 270 top
C132  SC100P50V2JN-3GP  [C402H22]  156.24 81.15 180 top
C134  SC100P50V2JN-3DLGP  [C402H22]  172.42 83.31 180 top
C138  SC4D7U6D3V3KX-DLGP  [C603H36]  168.54 81.53 180 top
C139  SC4D7U6D3V3KX-DLGP  [C603H36]  170.47 80.39 90 top
C140  SC2D2U10V3KX-1DLGP-U  [C603H36]  167.93 78.38 180 top
C141  SCD01U50V2KX-1DLGP  [C402H22]  16.29 140.46 270 top
C142  SCD01U50V2KX-1DLGP  [C402H22]  16.29 141.48 270 top
C144  SC10U10V5KX-2DLGP  [C805H50]  170.85 77.98 180 top
C145  SCD1U16V2KX-3DLGP  [C402H22]  169.2 78.11 0 top
C146  SC10U10V5KX-2DLGP  [C805H50]  169.96 75.18 90 top
C147  SCD1U16V2KX-3DLGP  [C402H22]  167.67 75.18 0 top
C149  SCD01U50V2KX-1DLGP  [C402H22]  16.29 142.49 270 top
C150  SC1U10V2KX-1DLGP  [C402H22]  157.01 75.82 180 top
C151  SCD01U50V2KX-1DLGP  [C402H22]  16.29 143.51 270 top
C154  SC10U10V5KX-2DLGP  [C805H50]  168.05 72.14 0 top
C155  SC10U10V5KX-2DLGP  [C805H50]  170.09 72.14 0 top
C157  SC100P50V2JN-3DLGP  [C402H22]  163.48 71.25 0 top
C159  SC100P50V2JN-3DLGP  [C402H22]  162.09 70.74 90 top
C160  SC100P50V2JN-3DLGP  [C402H22]  158.66 71.25 0 top
C170  SC1U10V2KX-1GP  [C402H22]  161.58 64.52 90 top
C190  SC1U16V3KX-4DLGP  [C603H36]  148.5 56.39 180 bottom
C192  SC1U25V3KX-1-DLGP  [C603H36]  162.47 28.45 90 top
C193  SC1U25V3KX-1-DLGP  [C603H36]  162.47 27.18 90 top
C194  SC100P50V2JN-3DLGP  [C402H22]  131.86 60.58 90 top
C197  SCD1U16V2KX-3DLGP  [C402H22]  138.72 56.52 90 top
C198  SCD027U50V3KX-DL-GP  [C603H36]  156.75 24.51 180 top
C199  SCD027U50V3KX-DL-GP  [C603H36]  161.32 32 270 top
C200  SCD027U50V3KX-DL-GP  [C603H36]  161.32 30.73 270 top
C202  SC4D7U6D3V3KX-GP  [C603H36]  40.17 17.27 90 bottom
C203  SC100P50V2JN-3DLGP  [C402H22]  160.94 33.15 270 top
C204  SCD1U16V2KX-3DLGP  [C402H22]  36.13 14.07 270 bottom
C208  SC1U25V3KX-1-DLGP  [C603H36]  156.5 36.58 180 top
C209  SC4D7U6D3V3KX-GP  [C603H36]  47.02 18.54 180 top
C210  SCD027U50V3KX-DL-GP  [C603H36]  155.48 24.51 180 top
C211  SCD1U16V2KX-3DLGP  [C402H22]  148.09 49.02 0 bottom
C213  SCD1U16V2KX-3DLGP  [C402H22]  41.56 20.07 180 top
C222  SCD01U50V3KX-4GP  [C603H36]  141.51 17.91 0 bottom
C223  SCD22U25V3KX-DL-GP  [C603H36]  150.15 26.42 180 top
C224  SCD22U25V3KX-DL-GP  [C603H36]  150.15 34.8 0 top
C225  SCD68U16V3KX-GP-U  [C603H36]  142.27 23.24 270 top
C226  SC1000P50V3JN-DLGP  [C603H36]  142.27 18.41 270 top
C227  SC10U10V5KX-2GP  [C805H54]  87.41 22.61 0 top
C228  SCD22U25V3KX-DL-GP  [C603H36]  150.15 32 180 top
C229  SCD22U25V3KX-DL-GP  [C603H36]  150.15 29.21 0 top
C231  SCD1U16V2KX-3DLGP  [C402H22]  148.12 51.08 180 bottom
C235  SCD68U16V3KX-GP-U  [C603H36]  144.94 23.24 90 top
C236  SC1000P50V3JN-DLGP  [C603H36]  144.94 18.41 90 top
C238  SCD1U16V2KX-3DLGP  [C402H22]  32.04 26.16 180 top
C239  SCD01U50V3KX-4GP  [C603H36]  145.7 17.91 0 bottom
C243  SCD01U50V3KX-4GP  [C603H36]  151.16 17.91 0 bottom
C247  SCD68U16V3KX-GP-U  [C603H36]  150.53 23.24 90 top
C248  SC1000P50V3JN-DLGP  [C603H36]  150.4 18.41 90 top
C249  SCD1U50V3KX-GP  [C603H36]  90.46 24.26 270 top
C255  SCD68U16V3KX-GP-U  [C603H36]  147.61 23.24 270 top
C256  SC1000P50V3JN-DLGP  [C603H36]  147.73 18.41 270 top
C258  SCD1U50V3KX-DL-GP  [C603H35]  66.45 44.07 180 top
C260  SC1U25V3KX-1-DLGP  [C603H36]  66.33 33.78 90 top
C262  SCD01U50V2KX-1GP  [C402H22]  66.2 29.72 90 top
C263  SCD01U50V3KX-4GP  [C603H36]  146.97 17.91 0 bottom
C267  SC100P50V2JN-3DLGP  [C402H22]  83.09 39.62 90 top
C268  SC100P50V2JN-3DLGP  [C402H22]  83.6 38.1 180 top
C283  SC10U10V5KX-2DLGP  [C805H50]  40.42 103 90 bottom
C284  SCD1U16V2KX-3DLGP  [C402H22]  35.69 101.78 90 bottom
C289  SCD1U16V2KX-3DLGP  [C402H22]  40.67 101.55 90 bottom
C290  SCD1U16V2KX-3DLGP  [C402H22]  35.69 100.89 270 bottom
C291  SC22U6D3V5MX-2DLGP  [C805H54]  37.65 102.67 0 bottom
C292  SC10U10V5KX-2DLGP  [C805H50]  32.52 79.83 90 bottom
C293  SCD1U16V2KX-3DLGP  [C402H22]  33.03 82.17 90 bottom
C295  SCD1U16V2KX-3DLGP  [C402H22]  33.71 88.49 90 bottom
C296  SC10U10V5KX-2DLGP  [C805H50]  32.16 101.22 90 bottom
C297  SCD1U16V2KX-3DLGP  [C402H22]  37.45 89.03 180 bottom
C298  SCD1U16V2KX-3DLGP  [C402H22]  33.03 81.28 90 bottom
C299  SCD1U16V2KX-3DLGP  [C402H22]  33.71 89.38 270 bottom
C300  SCD1U16V2KX-3DLGP  [C402H22]  31.53 95.12 270 bottom
C301  SCD1U16V2KX-3DLGP  [C402H22]  31.53 96.01 270 bottom
C302  SCD1U16V2KX-3DLGP  [C402H22]  31.53 96.9 270 bottom
C303  SCD1U16V2KX-3DLGP  [C402H22]  31.53 97.79 270 bottom
C304  SCD1U16V2KX-3DLGP  [C402H22]  31.53 93.09 270 bottom
C305  SCD1U16V2KX-3DLGP  [C402H22]  31.53 92.2 270 bottom
C315  SC10U10V5KX-2GP  [C805H54]  44.99 124.84 90 top
C316  SCD1U16V2KX-3DLGP  [C402H22]  45.37 126.36 270 top
C326  SC180P50V2JN-1DLGP  [C402H22]  79.41 159 90 bottom
C330  SC180P50V2JN-1DLGP  [C402H22]  76.74 160.66 90 bottom
C337  SCD1U16V2KX-3DLGP  [C402H22]  131.35 165.99 90 bottom
C353  SCD1U16V2KX-3DLGP  [C402H22]  131.35 164.08 90 bottom
C356  SC180P50V2JN-1DLGP  [C402H22]  90.08 169.93 270 bottom
C392  SCD1U16V2KX-3DLGP  [C402H22]  131.35 162.18 90 bottom
C395  SC1U10V2KX-1DLGP  [C402H22]  86.14 153.9 270 bottom
C450  SC10U10V5KX-2DLGP  [C805H50]  167.29 88.01 180 bottom
C474  SC10U6D3V3MX-DL-GP  [C603H36]  161.3 81.05 180 bottom
C478  SC10U6D3V3MX-DL-GP  [C603H36]  162.52 81.05 180 bottom
C483  SCD1U16V2KX-3DLGP  [C402H22]  161.07 75.39 270 bottom
C485  SC10U6D3V3MX-DL-GP  [C603H36]  160.08 78.44 0 bottom
C493  SC10U6D3V3MX-GP  [C603H38]  160.84 76.45 270 bottom
C495  SCD1U16V2KX-3DLGP  [C402H22]  159.04 76.78 180 bottom
C509  SC10U6D3V3MX-GP  [C603H38]  156.97 74.41 90 bottom
C516  SCD1U16V2KX-3GP  [C402H22]  156.97 73.26 90 bottom
C521  SC1U16V3KX-2GP  [C603H36]  145.12 31.39 270 top
C524  SC2200P50V2KX-2DLGP  [C402H22]  142.43 51.92 0 bottom
C525  SCD1U16V2ZY-2GP  [C402H22]  152.81 49.02 270 bottom
C531  SC1KP50V2KX-1GP  [C402H22]  156.75 29.72 270 bottom
C542  SCD1U16V2ZY-2GP  [C402H22]  162.09 43.43 270 top
C543  SC10U25V5KX-DL-GP  [C805H58]  153.2 32.51 180 bottom
C545  SCD1U50V3KX-DL-GP  [C603H35]  153.2 35.81 270 top
C548  SC2D2U6D3V2MX-GP  [C402H22]  159.16 64.14 0 top
C549  SCD1U16V2KX-3DLGP  [C402H22]  158.28 64.14 0 top
C550  SCD1U16V2KX-3DLGP  [C402H22]  160.94 62.74 0 top
C551  SC10U25V5KX-DL-GP  [C805H58]  153.2 28.83 0 bottom
C552  SCD1U50V3KX-DL-GP  [C603H35]  152.18 25.27 180 top
C558  SCD1U16V2KX-3DLGP  [C402H22]  138.84 42.42 90 top
C562  SC1U10V2KX-1DLGP  [C402H22]  142.65 42.93 90 top
C565  SC22U6D3V5MX-2DLGP  [C805H54]  142.02 41.4 90 top
C570  SCD1U16V2KX-3DLGP  [C402H22]  40.42 13.41 90 bottom
C572  SCD1U16V2KX-3DLGP  [C402H22]  33.05 10.67 0 top
C574  SCD1U16V2KX-3DLGP  [C402H22]  42.45 14.22 90 top
C579  SC2D2U10V3KX-1DLGP-U  [C603H36]  42.96 9.53 270 top
C580  SCD1U16V2KX-3GP  [C402H22]  38.13 12.57 0 bottom
C582  SCD1U16V2KX-3DLGP  [C402H22]  37.5 27.18 90 top
C583  SCD1U16V2KX-3DLGP  [C402H22]  40.42 15.24 90 bottom
C584  SCD1U16V2KX-3DLGP  [C402H22]  40.42 12.52 90 bottom
C585  SCD1U16V2KX-3DLGP  [C402H22]  32.42 28.07 0 top
C587  SCD1U16V2KX-3DLGP  [C402H22]  36.74 17.53 180 bottom
C589  SC1KP50V2KX-1GP  [C402H22]  107.6 29.59 0 top
C591  SC1U10V2KX-1GP  [C402H22]  44.23 5.97 180 bottom
C592  SC10U10V5KX-2DLGP  [C805H50]  24.29 8.38 90 bottom
C593  SC1U10V2KX-1GP  [C402H22]  45.25 5.97 0 top
C595  SCD1U16V2KX-3DLGP  [C402H22]  39.66 5.97 180 bottom
C597  SCD1U50V3KX-DL-GP  [C603H35]  66.33 27.81 90 top
C714  SCD1U16V2KX-3DLGP  [C402H22]  107.09 31.11 90 top
C721  SCD1U16V2KX-3DLGP  [C402H22]  107.09 36.45 90 top
C857  SCD1U50V3KX-GP  [C603H36]  51.72 138.05 0 top
C862  SCD1U50V3KX-GP  [C603H36]  42.58 127.76 0 top
C863  SC1U10V2KX-1GP  [C402H22]  39.66 5.97 0 top
C864  SC1U10V2KX-1GP  [C402H22]  128.07 217.96 270 top
C865  SCD22U25V3KX-DL-GP  [C603H36]  38.77 143 270 top
C866  SC1U10V2KX-1GP  [C402H22]  92.62 14.86 180 bottom
C869  SCD1U16V2KX-3DLGP  [C402H22]  42.68 120.83 270 top
C871  SC1U10V2KX-1GP  [C402H22]  161.2 112.01 270 top
C872  SCD068U16V2KX-DL-GP  [C402H22]  108.75 18.41 0 top
C1491  SC1U10V2KX-1DLGP  [C402H22]  157.39 78.36 180 top
C1608  SC1KP50V2KX-1DLGP  [C402H22]  95.28 168.4 90 bottom
C1609  SCD1U16V2KX-3DLGP  [C402H22]  95.28 167.39 270 bottom
C1615  SC2D2U10V3KX-1DLGP-U  [C603H36]  128.56 208.66 270 bottom
C1616  SC1U10V2KX-1GP  [C402H22]  124.49 211.2 0 bottom
C1617  SCD1U16V2KX-3DLGP  [C402H22]  128.43 209.68 270 bottom
C1638  SC1U10V2KX-1DLGP  [C402H22]  88.04 138.18 90 top
C1639  SC1U10V2KX-1DLGP  [C402H22]  88.04 139.06 90 top
C1644  SC22U6D3V3MX-1-DL-GP  [C603H40]  79.03 160.66 270 bottom
C1645  SC22U6D3V3MX-1-DL-GP  [C603H40]  81.69 160.66 270 bottom
C1646  SC22U6D3V3MX-1-DL-GP  [C603H40]  76.23 168.4 0 bottom
C1647  SC22U6D3V3MX-1-DL-GP  [C603H40]  87.03 160.66 270 bottom
C1648  SC22U6D3V3MX-1-DL-GP  [C603H40]  84.36 160.66 270 bottom
C1649  SC22U6D3V3MX-1-DL-GP  [C603H40]  87.03 167.77 270 bottom
C1650  SC22U6D3V3MX-1-DL-GP  [C603H40]  84.36 167.77 270 bottom
C1651  SC22U6D3V3MX-1-DL-GP  [C603H40]  81.69 167.77 270 bottom
C1652  SC22U6D3V3MX-1-DL-GP  [C603H40]  79.03 167.77 270 bottom
C1653  SC22U6D3V3MX-1-DL-GP  [C603H40]  81.69 157.99 270 bottom
C1654  SC22U6D3V3MX-1-DL-GP  [C603H40]  84.36 157.99 90 bottom
C1655  SC22U6D3V3MX-1-DL-GP  [C603H40]  87.03 157.99 270 bottom
C1656  SC22U6D3V3MX-1-DL-GP  [C603H40]  79.03 157.99 90 bottom
C1657  SCD22U10V2KX-2-GP  [C402H22]  86.65 165.61 270 bottom
C1658  SCD22U10V2KX-2-GP  [C402H22]  84.23 165.61 270 bottom
C1659  SCD22U10V2KX-2-GP  [C402H22]  84.23 163.19 270 bottom
C1660  SCD22U10V2KX-2-GP  [C402H22]  79.41 163.19 270 bottom
C1661  SCD22U10V2KX-2-GP  [C402H22]  81.82 163.19 270 bottom
C1662  SCD22U10V2KX-2-GP  [C402H22]  81.82 165.61 270 bottom
C1663  SCD22U10V2KX-2-GP  [C402H22]  86.65 163.19 270 bottom
C1664  SCD22U10V2KX-2-GP  [C402H22]  79.41 165.61 270 bottom
C1665  SCD22U10V2KX-2-GP  [C402H22]  86.65 156.59 270 bottom
C1666  SCD22U10V2KX-2-GP  [C402H22]  81.82 155.7 90 bottom
C1667  SCD22U10V2KX-2-GP  [C402H22]  81.82 156.59 90 bottom
C1668  SCD22U10V2KX-2-GP  [C402H22]  79.41 156.59 90 bottom
C1669  SCD22U10V2KX-2-GP  [C402H22]  84.23 156.59 90 bottom
C1670  SCD22U10V2KX-2-GP  [C402H22]  86.65 159 270 bottom
C1671  SCD22U10V2KX-2-GP  [C402H22]  84.23 159 90 bottom
C1672  SCD22U10V2KX-2-GP  [C402H22]  81.82 159 270 bottom
C1673  SC22U6D3V3MX-1-DL-GP  [C603H40]  45.5 128.52 90 top
C1674  SC10U6D3V3MX-DL-GP  [C603H36]  84.11 155.17 270 bottom
C1677  SC10U6D3V3MX-DL-GP  [C603H36]  75.98 152.65 90 bottom
C1678  SC22U6D3V3MX-1-DL-GP  [C603H40]  90.58 164.08 90 bottom
C1679  SC22U6D3V3MX-1-DL-GP  [C603H40]  90.58 161.67 90 bottom
C1680  SC22U6D3V3MX-1-DL-GP  [C603H40]  90.46 168.91 90 bottom
C1681  SC22U6D3V3MX-1-DL-GP  [C603H40]  90.46 166.5 90 bottom
C1682  SC22U6D3V3MX-1-DL-GP  [C603H40]  90.58 159.38 90 bottom
C1683  SC22U6D3V3MX-1-DL-GP  [C603H40]  91.47 156.46 180 bottom
C1684  SC22U6D3V3MX-1-DL-GP  [C603H40]  95.16 156.46 180 bottom
C1685  SC22U6D3V3MX-1-DL-GP  [C603H40]  93.25 156.46 180 bottom
C1686  SC22U6D3V3MX-1-DL-GP  [C603H40]  93.02 172.09 0 bottom
C1687  SC22U6D3V3MX-1-DL-GP  [C603H40]  94.9 172.09 0 bottom
C1688  SC22U6D3V3MX-1-DL-GP  [C603H40]  91.85 172.09 0 bottom
C1689  SCD22U10V2KX-2-GP  [C402H22]  90.08 167.64 270 bottom
C1690  SCD22U10V2KX-2-GP  [C402H22]  90.2 165.23 270 bottom
C1691  SCD22U10V2KX-2-GP  [C402H22]  90.2 162.81 270 bottom
C1692  SCD22U10V2KX-2-GP  [C402H22]  90.2 160.53 270 bottom
C1693  SCD22U10V2KX-2-GP  [C402H22]  90.2 158.24 270 bottom
C1694  SCD22U10V2KX-2-GP  [C402H22]  90.08 170.81 270 bottom
C1695  SC10U6D3V3MX-DL-GP  [C603H36]  88.93 151.51 0 bottom
C1696  SCD22U10V2KX-2-GP  [C402H22]  72.68 161.42 90 bottom
C1697  SC180P50V2JN-1DLGP  [C402H22]  84.62 150.24 180 bottom
C1698  SC1U10V2KX-1DLGP  [C402H22]  92.87 12.83 0 top
C1699  SC1U10V2KX-1DLGP  [C402H22]  87.79 12.83 0 top
C1700  SC1U6D3V2KX-DLGP  [C402H22]  91.75 16.1 180 top
C1701  SCD1U16V2KX-3DLGP  [C402H22]  87.79 10.79 180 top
C1702  SC10U6D3V3MX-DL-GP  [C603H36]  39.91 144.27 270 top
C1703  SCD22U10V2KX-2-GP  [C402H22]  78.01 154.81 180 bottom
C1704  SC10U6D3V3MX-DL-GP  [C603H36]  87.66 151.51 0 bottom
C1705  SC10U6D3V3MX-DL-GP  [C603H36]  91.98 151.51 0 bottom
C1706  SC10U6D3V3MX-DL-GP  [C603H36]  106.71 150.37 0 bottom
C1707  SC10U6D3V3MX-DL-GP  [C603H36]  90.58 151.51 0 bottom
C1708  SCD22U10V2KX-2-GP  [C402H22]  95.16 151.89 0 bottom
C1714  SC10U6D3V3MX-DL-GP  [C603H36]  87.92 154.94 270 bottom
C1715  SC10U6D3V3MX-DL-GP  [C603H36]  82.84 148.84 90 bottom
C1716  SCD22U10V2KX-2-GP  [C402H22]  81.31 154.81 90 bottom
C1721  SC150P50V2KX-GP  [C402H22]  78.9 186.56 0 top
C1722  SC150P50V2KX-GP  [C402H22]  83.98 190.63 0 top
C1723  SCD1U16V2KX-3DLGP  [C402H22]  131.35 154.94 90 bottom
C1724  SC4D7U6D3V3KX-DLGP  [C603H36]  150.27 128.14 0 bottom
C1725  SC4D7U6D3V3KX-DLGP  [C603H36]  130.97 153.03 90 bottom
C1726  SCD1U10V2KX-5GP  [C402H22]  154.34 181.61 270 bottom
C1727  SC1KP50V2KX-1DLGP  [C402H22]  138.72 191.9 180 bottom
C1728  SC1U10V2KX-1DLGP  [C402H22]  140.5 191.9 0 bottom
C1729  SCD1U16V2KX-3GP  [C402H22]  130.97 127.25 90 bottom
C1730  SCD1U16V2KX-3GP  [C402H22]  130.34 128.27 90 bottom
C1731  SCD1U16V2KX-3DLGP  [C402H22]  139.61 191.9 180 bottom
C1732  SCD1U16V2KX-3DLGP  [C402H22]  149.13 128.14 0 bottom
C1733  SC100P50V2JN-3GP  [C402H22]  77.27 148.74 90 bottom
C1734  SC100P50V2JN-3GP  [C402H22]  80.93 135.13 270 top
C1735  SCD01U25V2KX-3GP  [C402H22]  56.8 159.64 270 top
C1736  SC1U10V2KX-1DLGP  [C402H22]  159.8 111.51 180 top
C1737  SCD1U16V2KX-3DLGP  [C402H22]  156.88 123.19 0 top
C1738  SC150P50V2JN-3DLGP  [C402H22]  54.77 149.1 0 top
C1739  SC1U10V2KX-1GP  [C402H22]  100.11 210.57 270 top
C1741  SCD22U10V2KX-2-GP  [C402H22]  84.13 153.62 180 bottom
C1742  SCD1U16V2KX-3DLGP  [C402H22]  122.08 224.54 90 top
C1743  SC10U6D3V3MX-DL-GP  [C603H36]  123.73 202.31 180 bottom
C1744  SC10U6D3V3MX-DL-GP  [C603H36]  125 202.31 180 bottom
C1745  SC2D2U10V3KX-1DLGP-U  [C603H36]  126.27 202.31 180 bottom
C1746  SCD1U16V2KX-3DLGP  [C402H22]  146.59 150.88 0 bottom
C1747  SCD1U16V2KX-3GP  [C402H22]  96.43 26.42 0 top
C1748  SC10U10V5KX-2GP  [C805H54]  100.36 24 90 top
C1752  SC10U10V5KX-2GP  [C805H54]  100.36 27.05 90 top
C1753  SCD1U16V2KX-3DLGP  [C402H22]  173.26 107.31 270 top
C1754  SCD1U16V2KX-3DLGP  [C402H22]  95.54 26.42 180 top
C1755  SCD068U16V2KX-DL-GP  [C402H22]  100.36 25.53 270 top
C1756  SC1KP50V2KX-1GP  [C402H22]  175.17 125.73 0 top
C1757  SCD1U16V2KX-3DLGP  [C402H22]  163.1 118.49 90 top
C1758  SCD1U16V2KX-3DLGP  [C402H22]  38.13 119.89 180 top
C1760  SCD1U16V2KX-3GP  [C402H22]  27.08 28.19 270 bottom
C1764  SCD01U50V2KX-1DLGP  [C402H22]  92.87 23.62 90 top
C1768  SCD1U25V3KX-GP  [C603H36]  58.71 143.64 180 top
C1769  SCD1U16V2KX-3DLGP  [C402H22]  90.08 23.11 90 top
C1770  SC10U10V5KX-2DLGP  [C805H50]  157.64 188.67 90 bottom
C1771  SC10U10V5KX-2DLGP  [C805H50]  157.64 190.68 90 bottom
C1773  SC10P50V2JN-4GP  [C402H22]  31.33 12.7 0 bottom
C1774  SC10P50V2JN-4GP  [C402H22]  32.21 12.7 0 bottom
C1780  SC100P50V2JN-3DLGP  [C402H22]  164.19 85.45 0 bottom
C1796  SC1U16V3KX-2GP  [C603H36]  143.8 73.15 0 top
C1797  SC1U16V3KX-2GP  [C603H36]  143.04 77.72 0 bottom
C1798  SC1U10V2KX-1GP  [C402H22]  33.82 7.98 180 bottom
C1799  SC15P50V2JN-DL-GP  [C402H22]  37.75 10.29 90 top
C1800  SC12P50V2JN-DL-GP  [C402H22]  34.83 10.54 270 top
C1801  SC1U25V3KX-1-DLGP  [C603H36]  36.3 13.06 270 bottom
C1802  SC2D2U10V3KX-1DLGP-U  [C603H36]  71.28 29.08 90 top
C1803  SC4D7U6D3V3KX-GP  [C603H36]  46.26 15.88 270 top
C1804  SC4D7U6D3V3KX-GP  [C603H36]  48.29 18.54 180 top
C1805  SCD1U16V2KX-3DLGP  [C402H22]  35.47 20.07 180 top
C1806  SCD1U16V2KX-3DLGP  [C402H22]  71.28 30.23 90 top
C1807  SCD1U25V3KX-GP  [C603H36]  46.26 14.61 270 top
C1808  SCD1U16V2KX-3DLGP  [C402H22]  34.58 20.07 180 top
C1809  SCD1U16V2KX-3DLGP  [C402H22]  65.44 179.71 270 top
C1810  SCD1U16V2KX-3DLGP  [C402H22]  65.44 181.48 270 top
C1811  SCD1U16V2KX-3DLGP  [C402H22]  65.44 178.82 270 top
C1812  SCD1U16V2KX-3DLGP  [C402H22]  65.44 183.26 270 top
C1813  SCD1U16V2KX-3DLGP  [C402H22]  65.44 180.59 270 top
C1814  SCD1U16V2KX-3DLGP  [C402H22]  65.44 182.37 270 top
C1815  SCD1U16V2KX-3DLGP  [C402H22]  65.44 184.15 270 top
C1816  SCD1U16V2KX-3DLGP  [C402H22]  138.72 45.59 180 top
C1817  SCD1U16V2KX-3DLGP  [C402H22]  139.1 49.15 270 bottom
C1818  SCD1U16V2KX-3DLGP  [C402H22]  139.1 49.15 90 top
C1820  SCD1U16V2KX-3DLGP  [C402H22]  144.43 60.33 0 bottom
C1821  SC1U10V2KX-1DLGP  [C402H22]  142.91 58.29 270 bottom
C1823  SCD1U16V2ZY-2GP  [C402H22]  120.25 48.77 270 top
C1824  SC22U6D3V5MX-2DLGP  [C805H54]  159.29 44.07 180 bottom
C1825  SC1U10V2KX-1DLGP  [C402H22]  139.1 50.11 90 bottom
C1826  SCD1U16V2KX-3DLGP  [C402H22]  158.4 46.35 270 bottom
C1827  SC1U10V2KX-1GP  [C402H22]  39 86.49 180 bottom
C1828  SCD22U10V2KX-2-GP  [C402H22]  76.61 154.05 90 bottom
C1829  SC1U10V2KX-1DLGP  [C402H22]  141.94 8.31 270 top
C1830  SC1U10V2KX-1DLGP  [C402H22]  142.2 5.64 270 top
C1831  SC1U6D3V2KX-DLGP  [C402H22]  141.94 9.19 270 top
C1832  SCD1U16V2KX-3DLGP  [C402H22]  149.59 8.38 90 top
C1833  SC10U10V5KX-2GP  [C805H54]  146.21 10.16 0 bottom
C1834  SCD1U16V2KX-3DLGP  [C402H22]  149.59 5.71 90 top
C1835  SC10U10V5KX-2GP  [C805H54]  149.13 10.16 0 bottom
C1836  SC1KP50V2KX-1DLGP  [C402H22]  149.59 6.6 90 top
C1837  SC1KP50V2KX-1DLGP  [C402H22]  149.59 7.49 90 top
C1870  SCD01U50V2KX-1DLGP  [C402H22]  100.11 211.84 90 top
C1871  SC180P50V2JN-1DLGP  [C402H22]  137.19 154.94 90 bottom
C1872  SCD22U10V2KX-2-GP  [C402H22]  137.19 160.27 90 bottom
C1873  SCD22U10V2KX-2-GP  [C402H22]  137.19 156.84 90 bottom
C1874  SCD22U10V2KX-2-GP  [C402H22]  137.19 162.18 90 bottom
C1875  SCD22U10V2KX-2-GP  [C402H22]  137.19 164.08 90 bottom
C1876  SC180P50V2JN-1DLGP  [C402H22]  137.19 165.99 90 bottom
C1877  SCD1U16V2KX-3DLGP  [C402H22]  38.41 76.15 0 bottom
C1925  SC10U10V5KX-2GP  [C805H54]  88.43 6.86 0 top
C1926  SCD1U16V2KX-3DLGP  [C402H22]  92.87 10.79 180 top
C1927  SC10U10V5KX-2GP  [C805H54]  92.24 6.86 0 top
C1928  SC1KP50V2KX-1DLGP  [C402H22]  89.82 7.62 0 top
C1929  SC1KP50V2KX-1DLGP  [C402H22]  90.84 7.62 0 top
C1930  SCD1U16V2KX-3GP  [C402H22]  85.76 209.17 180 bottom
C1934  SC22U6D3V3MX-1-DL-GP  [C603H40]  79.03 170.31 270 bottom
C1935  SC22U6D3V3MX-1-DL-GP  [C603H40]  81.69 170.31 270 bottom
C1936  SC22U6D3V3MX-1-DL-GP  [C603H40]  84.36 170.31 270 bottom
C1937  SC180P50V2JN-1GP  [C402H22]  83.6 172.34 270 bottom
C1938  SC22U6D3V3MX-1-DL-GP  [C603H40]  87.03 170.31 270 bottom
C1939  SCD22U10V2KX-2-GP  [C402H22]  85.76 172.34 270 bottom
C1940  SCD22U10V2KX-2-GP  [C402H22]  87.79 172.34 270 bottom
C1941  SCD22U10V2KX-2-GP  [C402H22]  81.19 172.34 270 bottom
C1942  SCD22U10V2KX-2-GP  [C402H22]  87.79 173.23 270 bottom
C1943  SCD22U10V2KX-2-GP  [C402H22]  78.9 172.34 270 bottom
C1944  SCD22U10V2KX-2-GP  [C402H22]  85.76 173.23 270 bottom
C1945  SCD22U10V2KX-2-GP  [C402H22]  83.6 173.23 270 bottom
C1946  SCD22U10V2KX-2-GP  [C402H22]  81.19 173.23 270 bottom
C1947  SC22U6D3V3MX-1-DL-GP  [C603H40]  79.03 174.88 270 bottom
C1948  SC22U6D3V3MX-1-DL-GP  [C603H40]  81.69 174.88 270 bottom
C1949  SC22U6D3V3MX-1-DL-GP  [C603H40]  87.03 174.88 270 bottom
C1950  SC22U6D3V3MX-1-DL-GP  [C603H40]  76.49 176.53 0 bottom
C1951  SC22U6D3V3MX-1-DL-GP  [C603H40]  84.36 174.88 270 bottom
C1952  SCD22U10V2KX-2-GP  [C402H22]  78.9 173.23 270 bottom
C1953  SC10U6D3V3MX-GP  [C603H38]  79.03 153.42 180 bottom
C1954  SCD22U10V2KX-2-GP  [C402H22]  79.41 155.57 90 bottom
C1956  SC10U6D3V3MX-GP  [C603H38]  160.56 215.39 0 bottom
C1957  SC1U10V2KX-1GP  [C402H22]  76.44 151.54 90 bottom
C1958  SCD1U10V2KX-5GP  [C402H22]  154.34 184.66 270 bottom
C1959  SC1KP50V2KX-1DLGP  [C402H22]  147.23 191.9 0 bottom
C1960  SC1U10V2KX-1DLGP  [C402H22]  148.12 191.9 0 bottom
C1961  SCD1U16V2KX-3DLGP  [C402H22]  154.72 165.99 270 bottom
C1962  SC180P50V2JN-1DLGP  [C402H22]  154.72 164.08 270 bottom
C1963  SCD22U10V2KX-2-GP  [C402H22]  154.72 162.18 270 bottom
C1964  SCD22U10V2KX-2-GP  [C402H22]  154.72 156.97 270 bottom
C1965  SCD22U10V2KX-2-GP  [C402H22]  154.72 154.94 270 bottom
C1966  SCD1U16V2KX-3DLGP  [C402H22]  154.72 159.38 270 bottom
C1967  SCD1U16V2KX-3DLGP  [C402H22]  148.62 165.99 270 bottom
C1968  SCD1U16V2KX-3DLGP  [C402H22]  148.62 164.08 270 bottom
C1969  SCD1U16V2KX-3DLGP  [C402H22]  148.62 162.18 270 bottom
C1970  SCD1U16V2KX-3DLGP  [C402H22]  148.62 156.97 270 bottom
C1971  SC4D7U6D3V3KX-DLGP  [C603H36]  136.94 127.25 180 bottom
C1972  SC4D7U6D3V3KX-DLGP  [C603H36]  154.97 153.03 270 bottom
C1973  SC4D7U6D3V3KX-DLGP  [C603H36]  147.99 153.03 270 bottom
C1974  SCD22U10V2KX-2-GP  [C402H22]  148.62 160.27 270 bottom
C1975  SCD1U16V2KX-3GP  [C402H22]  146.08 128.14 270 bottom
C1976  SCD1U16V2KX-3GP  [C402H22]  142.65 125.98 90 bottom
C1977  SCD1U16V2KX-3DLGP  [C402H22]  138.72 127.25 180 bottom
C1978  SC180P50V2JN-1DLGP  [C402H22]  148.62 154.94 270 bottom
C1979  SCD1U16V2KX-3DLGP  [C402H22]  152.18 150.88 0 bottom
C1980  SC1KP50V2KX-1DLGP  [C402H22]  151.29 150.88 0 bottom
C1981  SC1KP50V2KX-1DLGP  [C402H22]  145.45 191.9 180 bottom
C1982  SCD1U16V2KX-3DLGP  [C402H22]  146.34 191.9 180 bottom
C3131  SC100P3KV8JN-4-GP  [C1808H87]  64.04 19.56 0 bottom
C3366  SCD1U16V2KX-3DLGP  [C402H22]  127.92 41.53 180 top
C3367  SC10U10V5KX-2DLGP  [C805H50]  134.27 51.31 0 bottom
C3368  SCD1U16V2KX-3DLGP  [C402H22]  138.33 32.46 270 top
C3369  SCD1U16V2KX-3DLGP  [C402H22]  138.33 36.01 270 top
C3370  SCD1U16V2KX-3DLGP  [C402H22]  138.33 34.24 270 top
C3371  SCD1U16V2KX-3DLGP  [C402H22]  138.33 33.35 270 top
C3372  SCD1U16V2KX-3DLGP  [C402H22]  138.33 35.13 270 top
C3373  SCD1U16V2KX-3DLGP  [C402H22]  138.33 36.9 270 top
C3374  SCD1U16V2KX-3DLGP  [C402H22]  138.33 38.68 270 top
C3375  SCD1U16V2KX-3DLGP  [C402H22]  138.33 37.79 270 top
C3376  SCD01U50V2KX-1DLGP  [C402H22]  136.93 29.59 180 top
C3377  SCD1U16V2KX-3DLGP  [C402H22]  128.8 29.6 0 top
C3378  SCD1U16V2KX-3DLGP  [C402H22]  129.69 41.54 180 top
C3379  SCD1U16V2KX-3DLGP  [C402H22]  136.68 41.54 180 top
C3380  SCD01U50V2KX-1DLGP  [C402H22]  133.88 29.6 0 top
C3381  SCD01U50V2KX-1DLGP  [C402H22]  135.8 41.48 0 top
C3382  SCD1U16V2KX-3DLGP  [C402H22]  135.8 41.48 0 bottom
C3383  SCD1U16V2KX-3DLGP  [C402H22]  128.81 41.53 180 top
C3452  SCD01U50V2KX-1DLGP  [C402H22]  49.82 17.78 180 top
C3453  SCD1U16V2KX-3DLGP  [C402H22]  39.02 12.83 0 bottom
C3454  SCD1U16V2KX-3DLGP  [C402H22]  38.51 20.07 180 top
C3455  SCD1U25V2KX-1-DL-GP  [C402H22]  36.69 32.03 0 top
C3456  SCD1U25V2KX-LL-GP  [C402H22]  39.15 34.92 180 top
C3457  SCD01U50V2KX-1DLGP  [C402H22]  40.95 35.86 270 top
C3458  SCD01U50V2KX-1DLGP  [C402H22]  40.8 38.1 270 top
C3459  SC10U25V5KX-DL-GP  [C805H58]  49.94 43.05 90 top
C3460  SC10U25V5KX-DL-GP  [C805H58]  49.94 45.09 90 top
C4101  SC1U10V2KX-1DLGP  [C402H22]  94.52 52.2 180 bottom
C4102  SC1U10V2KX-1DLGP  [C402H22]  107.48 55.63 180 top
C6701  SCD1U16V2KX-3DLGP  [C402H22]  81.92 68.83 180 top
C6702  SCD1U16V2KX-3DLGP  [C402H22]  81.92 70.76 0 top
C6703  SC10U6D3V3MX-GP  [C603H38]  75.09 69.62 270 top
C6712  SCD22U10V2KX-2-GP  [C402H22]  160.43 209.68 180 bottom
C6714  SC10U6D3V3MX-DL-GP  [C603H36]  159.29 209.55 180 bottom
C6715  SC10U6D3V3MX-DL-GP  [C603H36]  159.29 215.39 0 bottom
C6718  SCD1U25V3KX-DLGP  [C603H36]  65.79 46.13 270 top
C6719  SCD1U25V3KX-DLGP  [C603H36]  69.27 29.69 180 top
C6720  SCD1U25V3KX-DLGP  [C603H36]  36.61 52.45 90 bottom
C6721  SCD1U16V2KX-3DLGP  [C402H22]  128.81 27.18 180 top
C6722  SC100P50V2JN-3DLGP  [C402H22]  32.8 20.95 0 top
C6724  SCD01U25V2KX-3DLGP  [C402H22]  83.6 58.29 180 bottom
C6725  SCD1U10V2KX-4GP  [C402H20]  88.93 54.23 270 bottom
C6726  SC4D7P50V2CN-1-DL-GP  [C402H22]  93.53 36.96 0 top
C6727  SC4D7P50V2CN-1-DL-GP  [C402H22]  92.11 36.96 0 top
C6728  SC4D7P50V2CN-1-DL-GP  [C402H22]  94.39 36.96 0 top
C6729  SC4D7P50V2CN-1-DL-GP  [C402H22]  95.84 36.96 0 top
C9006  SC1U10V2KX-1DLGP  [C402H22]  106.46 96.57 0 bottom
C9007  SC10U6D3V3MX-DL-GP  [C603H36]  71.03 87.05 0 top
C9008  SC100P50V2JN-3GP  [C402H22]  59.09 88.72 90 top
C9009  SC10U6D3V3MX-DL-GP  [C603H36]  63.43 98.81 180 top
C9010  SCD1U16V2KX-3DLGP  [C402H22]  78.77 103.17 270 bottom
C9011  SCD1U16V2KX-3DLGP  [C402H22]  75.47 104.78 180 bottom
C9012  SC10U6D3V3MX-DL-GP  [C603H36]  77.25 101.09 90 bottom
C9013  SCD1U16V2KX-3DLGP  [C402H22]  74.07 103.38 270 bottom
C9014  SC10U6D3V3MX-DL-GP  [C603H36]  62.03 98.81 180 top
C9015  SC10U6D3V3MX-DL-GP  [C603H36]  67.37 96.7 270 top
C9016  SCD1U16V2KX-3DLGP  [C402H22]  67.06 97.76 270 top
C9017  SC10U6D3V3MX-DL-GP  [C603H36]  75.34 96.65 180 bottom
C9018  SCD1U16V2KX-3DLGP  [C402H22]  74.58 106.55 0 bottom
C9019  SCD1U16V2KX-3DLGP  [C402H22]  67.09 95.12 0 top
C9020  SC10U6D3V3MX-DL-GP  [C603H36]  74.12 96.65 180 bottom
C9021  SCD1U16V2KX-3DLGP  [C402H22]  78.77 102.29 270 bottom
C9022  SCD1U16V2KX-3DLGP  [C402H22]  64.5 99.19 180 top
C9023  SC10U6D3V3MX-DL-GP  [C603H36]  60.76 98.81 180 top
C9024  SC10P50V2JN-4DLGP  [C402H22]  66.25 104.11 180 top
C9025  SC10P50V2JN-4DLGP  [C402H22]  67.22 101.47 0 top
C9026  SCD01U50V2KX-1DLGP  [C402H22]  64.55 106.3 90 top
C9027  SCD01U50V2KX-1DLGP  [C402H22]  64.55 105.28 90 top
C9028  SCD01U50V2KX-1DLGP  [C402H22]  64.55 107.31 90 top
C9029  SCD01U50V2KX-1DLGP  [C402H22]  64.55 108.2 90 top
C9031  SCD1U16V2KX-3DLGP  [C402H22]  106 101.42 180 bottom
C9032  SCD1U16V2KX-3DLGP  [C402H22]  107.09 103.89 0 bottom
C9034  SC4D7U6D3V3KX-DLGP  [C603H36]  109.63 105.03 0 bottom
C9035  SC4D7U6D3V3KX-DLGP  [C603H36]  109.68 99.64 180 bottom
C9036  SC1U10V2KX-1DLGP  [C402H22]  108.36 93.09 180 top
C9037  SC1U10V2KX-1GP  [C402H22]  118.75 99.92 0 bottom
C9038  SCD1U16V2KX-3DLGP  [C402H22]  74.07 104.27 270 bottom
C9039  SC10U6D3V3MX-DL-GP  [C603H36]  74.46 101.09 270 bottom
C9040  SCD1U16V2KX-3DLGP  [C402H22]  74.58 102.36 270 bottom
C9041  SC1U10V2KX-1DLGP  [C402H22]  109.66 89.31 0 top
CN1  DVDCON2-3  [14300002]  77.64 110.99 0 top
CONVT1  CLX-CON10-10-GP  [CI1410M1HRL-NH]  25 36.65 270 top
CPU1  CARRIZO-L-GP  [BGA968M2937H74]  83 165 0 top
D1  1SS355-4-GP  [SOD323AKH38]  14.26 218.69 180 top
D4  IP4223CZ6-1-GP  [SOT-6H44]  168.25 107.6 270 top
D16  P6SMB27A-1-GP  [DO214AAAK-1121H97]  62.52 26.67 180 top
D19  BAV99GP-GP  [SOT23-2D4-312H48]  62.72 36.4 180 bottom
D20  BAT54A-12-GP  [SOT23-2D4-312H44]  60.23 146.18 180 top
D21  AZ2015-01H-GP  [SOD523AKH28]  164.37 88.06 0 bottom
D23  BAT54C-11-GP  [SOT23-2D4-312H44]  73.06 49.07 90 top
D24  IP4223CZ6-1-GP  [SOT-6H44]  93.97 29.97 180 top
D31  1SS355-4-GP  [SOD323AKH38]  131.61 25.91 270 top
D32  BX310F-R1-00000-GP  [D4724AKH44]  37.75 41.58 270 top
D33  CH551H-30PT-GP  [SOD80CH36]  73.31 46.15 270 top
DCIN1  DC-JACK345-GP  [2DC3115-000111F]  53.25 25.53 270 top
DCIN2  ACES-CONN14G-GP  [88314-077N]  55.64 33.67 180 top
DIMM1  DDR3-204P-262-GP-U  [AS0A621-J4R6-7H-U]  135.3 158.9 90 top
DIMM2  DDR3-204P-142-GP-U  [AS0A626-J8R6-7H]  150.5 158.9 90 top
F1  POLYSW-1D5A6V-12-GP  [POLYSW-2114H30]  160.31 194.56 180 bottom
F2  POLYSW-2A6V-7-GP  [POLYSW-2114H30]  39.53 107.44 270 bottom
F3  POLYSW-1D5A6V-12-GP  [POLYSW-2114H30]  161.75 190.53 90 bottom
F5  POLYSW-2A6V-7-GP  [POLYSW-2114H30]  6.13 210.44 0 bottom
F6  POLYSW-1D5A6V-12-GP  [POLYSW-2114H30]  161.7 142.75 0 top
F12  POLYSW-2A6V-7-GP  [POLYSW-2114H30]  105.82 18.67 180 top
F13  POLYSW-1D5A6V-12-GP  [POLYSW-2114H30]  107.09 32.77 270 top
F14  POLYSW-2A6V-7-GP  [POLYSW-2114H30]  169.07 124.71 90 top
F15  POLYSW-1D5A6V-12-GP  [POLYSW-2114H30]  24.29 6.22 270 bottom
F16  FUSE-3A32V-26-GP  [FUSE-1608H22]  50.58 49.07 270 top
FANC3  FOX-CON4-30-GP  [HF1804H]  14 211 270 top
G5  COPPER-CLOSE-GP-U  [CON2C-U]  141.77 36.83 180 top
H1  HOLE237R158-GP  [HOLE237R158]  94.38 192.31 180 top
H2  HOLE237R158-GP  [HOLE237R158]  62.39 165.12 180 top
H3  HOLE237R158-GP  [HOLE237R158]  94.38 137.93 180 top
H4  HOLE237R158-GP  [HOLE237R158]  69 123.75 180 top
H5  HOLE237R158-GP  [HOLE237R158]  94.39 76.25 180 top
H6  GEN8D5X8R5X4D5-8-F-A-GP  [GEN8D5X8R5X4D5-8-F-A]  165 225 270 top
H7  GEN315R138-8-F-A-1-GP  [GEN315R138-8-F-A-1]  5 160 180 top
H9  GEN8D5X8R5X4D5-8-F-A-GP  [GEN8D5X8R5X4D5-8-F-A]  25 49.15 180 top
H10  GEN315R178-8-F-A-3-GP  [GEN315R178-8-F-A-1]  165 20 180 top
H11  GEN315R138-8-F-A-2-S-GP  [GEN315R138-8-F-A-2-S]  172.5 64.43 180 top
HDD1  SKT-SATA7P-184-GP-U  [15-02070-5A61-A]  12 142 270 top
HDMI1  SKT-HDMI22-12-GP  [SKT-HDMI22-150077]  113.99 37.03 270 top
HDMI2  ARG-CON20-GP  [LVDFH-02004-TP00]  118.69 37.07 270 top
HDT1  SMC-CONN20A-1-GP  [ASP-137098-05]  94.78 213.74 90 top
HS6  STF256R109H99-GP  [STF256R109H99]  144.25 214 180 top
L1  HCB2012KF-600T30-GP  [L20125H42]  35.97 107.44 270 bottom
L2  IND-2D2UH-250-GP-U  [L3030-2709H41]  31.83 104.65 0 bottom
L4  FILTER-4P-123-GP  [L125100-4P-1H36]  165.64 117.98 180 top
L5  FILTER-4P-123-GP  [L125100-4P-1H36]  165.64 115.7 180 top
L10  MHC1608S221NBP-GP  [L603H38]  153.2 37.08 90 top
L15  BLM15BD102SN1D-GP  [L402H22]  55.48 35.25 180 bottom
L16  HCB1608KF-800T30-GP  [L603H38]  39.99 105.71 270 bottom
L17  HCB1608KF-800T30-GP  [L603H38]  32.72 78.26 270 bottom
L19  HCB1608KF-800T30-GP  [L603H38]  165.64 88.27 180 bottom
L20  MCB1005S121FBP-GP  [L402H24]  82.58 38.1 180 top
L21  MCB1005S121FBP-GP  [L402H24]  158.86 74.85 0 bottom
L31  HCB2012KF-601T20-GP  [L20125H42]  142.53 20.83 0 top
L32  HCB2012KF-601T20-GP  [L20125H42]  144.69 20.83 0 top
L33  HCB2012KF-601T20-GP  [L20125H42]  150.15 20.83 0 top
L34  HCB2012KF-601T20-GP  [L20125H42]  147.99 20.83 0 top
L46  -  [0R0805-PAD]  107.09 34.92 270 top
L54  MCB1005S121FBP-GP  [L402H24]  157.51 84.71 270 top
L55  FCM1608KF-2-GP-U  [L1608-UH38]  107.6 19.05 180 top
L56  FILTER-4P-123-GP  [L125100-4P-1H36]  165.64 96.52 180 top
L57  FILTER-4P-123-GP  [L125100-4P-1H36]  165.64 94.23 180 top
L60  MHC1608S181NBP-GP  [L603H38]  141.77 39.75 90 top
L61  IND-33UH-83-GP  [L8080-6522-1H166]  43.01 47.8 270 top
L62  MCB1005S121FBP-GP  [L402H24]  84.74 37.21 180 top
L4101  BLM15HG102SN1D-GP  [L402H22]  106.08 54.86 180 top
L4102  FILTER-4P-123-GP  [L125100-4P-1H36]  18.83 140.84 0 top
L4103  FILTER-4P-123-GP  [L125100-4P-1H36]  18.83 143 0 top
LED2  LED-O-23-GP  [LED1608AKH30]  95.16 7.24 180 top
LED3  LED-O-23-GP  [LED1608AKH30]  168.05 128.91 90 top
LOUT1  AUDIO-JK419-GP  [JAC331-0140A8B-9H]  76.93 37.66 90 top
LPC1  FOX-CONN14A-S1-GP  [HL5507F]  120.28 55.09 0 top
LVDS1  ACES-CON30-21-GP  [50524-0300N-001]  36.8 95 270 top
MEMCD1  SKT-SDCARD-52-GP  [156-5101902601]  174.65 144.79 90 top
NGFF1  SKT-MINI67P-3-GP-U1  [2199230-7]  116 214 270 top
NOREF  *  [unnamed]  101.76 136.14 0 top
